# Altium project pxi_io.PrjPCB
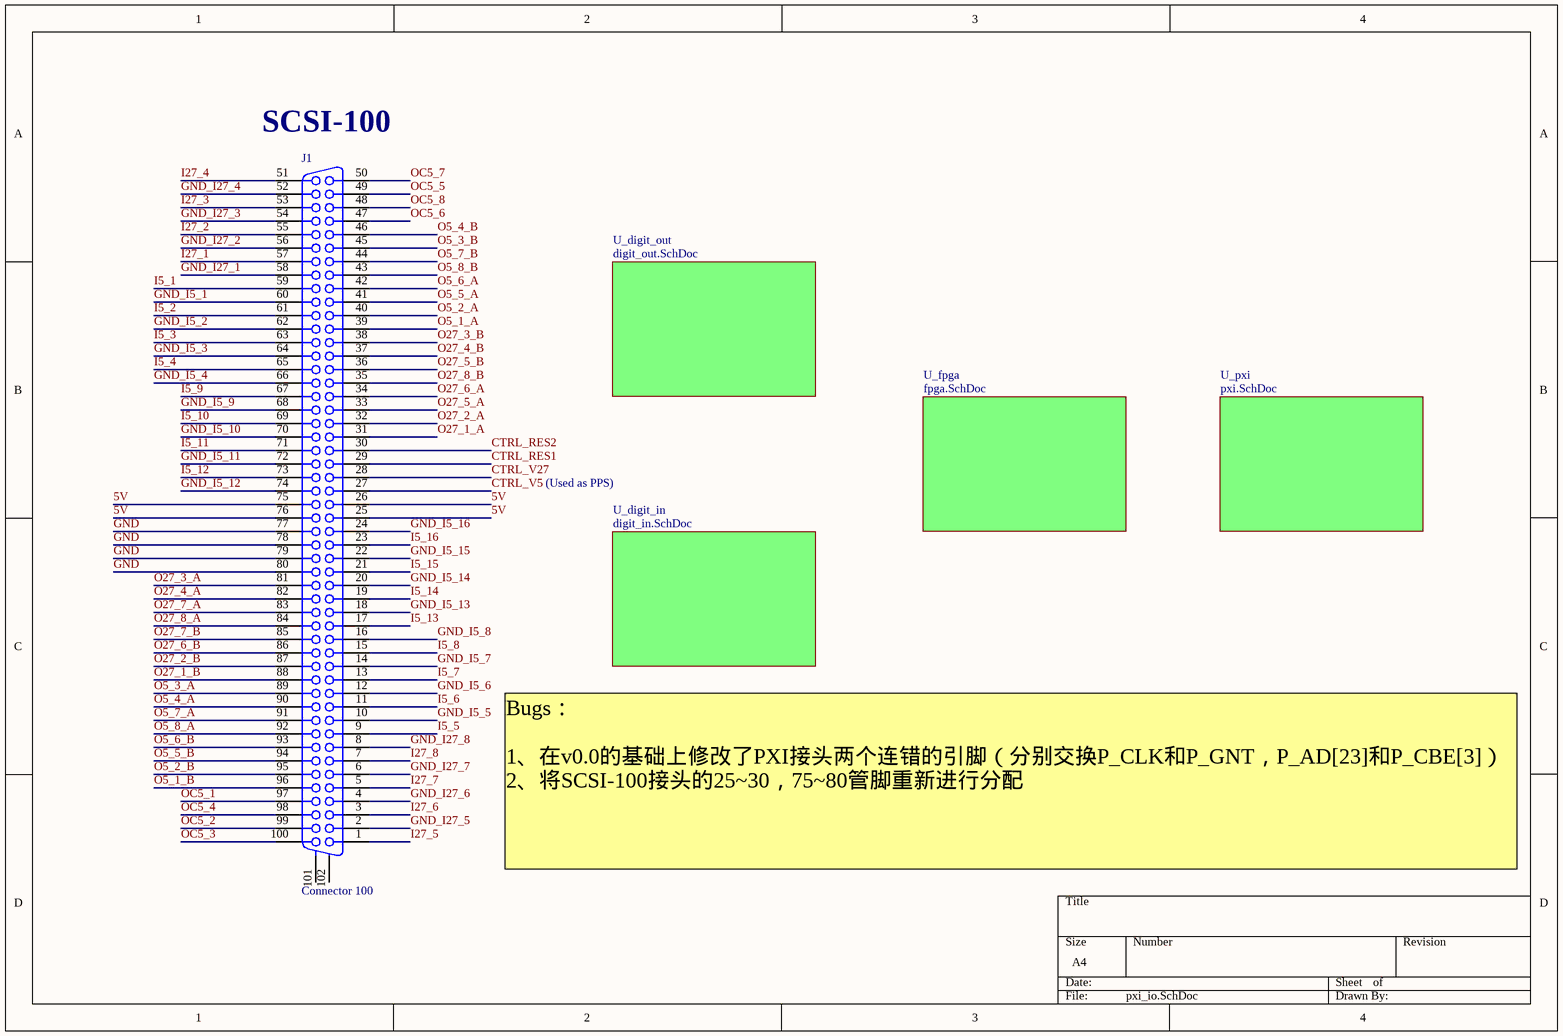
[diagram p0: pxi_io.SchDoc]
5 sheets, 257 parts. Net scope: global (net labels, ports and power ports of the same name join across sheets).
Board file: pxi_io.PcbDoc
Sheets:
  pxi_io.SchDoc
    U_fpga = fpga.SchDoc
    U_digit_out = digit_out.SchDoc
    U_digit_in = digit_in.SchDoc
    U_pxi = pxi.SchDoc

## Sheet pxi_io.SchDoc
size A4

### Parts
J1  Connector 100  [SCSI-100]

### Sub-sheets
U_digit_in = digit_in.SchDoc: no entries
U_digit_out = digit_out.SchDoc: no entries
U_fpga = fpga.SchDoc: no entries
U_pxi = pxi.SchDoc: no entries

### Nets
5V: J1.25 J1.26 J1.75 J1.76
GND: J1.77 J1.78 J1.79 J1.80
CTRL_RES1: J1.29
CTRL_RES2: J1.30
CTRL_V5: J1.27
CTRL_V27: J1.28
GND_I5_1: J1.60
GND_I5_2: J1.62
GND_I5_3: J1.64
GND_I5_4: J1.66
GND_I5_5: J1.10
GND_I5_6: J1.12
GND_I5_7: J1.14
GND_I5_8: J1.16
GND_I5_9: J1.68
GND_I5_10: J1.70
GND_I5_11: J1.72
GND_I5_12: J1.74
GND_I5_13: J1.18
GND_I5_14: J1.20
GND_I5_15: J1.22
GND_I5_16: J1.24
GND_I27_1: J1.58
GND_I27_2: J1.56
GND_I27_3: J1.54
GND_I27_4: J1.52
GND_I27_5: J1.2
GND_I27_6: J1.4
GND_I27_7: J1.6
GND_I27_8: J1.8
I5_1: J1.59
I5_2: J1.61
I5_3: J1.63
I5_4: J1.65
I5_5: J1.9
I5_6: J1.11
I5_7: J1.13
I5_8: J1.15
I5_9: J1.67
I5_10: J1.69
I5_11: J1.71
I5_12: J1.73
I5_13: J1.17
I5_14: J1.19
I5_15: J1.21
I5_16: J1.23
I27_1: J1.57
I27_2: J1.55
I27_3: J1.53
I27_4: J1.51
I27_5: J1.1
I27_6: J1.3
I27_7: J1.5
I27_8: J1.7
O5_1_A: J1.39
O5_1_B: J1.96
O5_2_A: J1.40
O5_2_B: J1.95
O5_3_A: J1.89
O5_3_B: J1.45
O5_4_A: J1.90
O5_4_B: J1.46
O5_5_A: J1.41
O5_5_B: J1.94
O5_6_A: J1.42
O5_6_B: J1.93
O5_7_A: J1.91
O5_7_B: J1.44
O5_8_A: J1.92
O5_8_B: J1.43
O27_1_A: J1.31
O27_1_B: J1.88
O27_2_A: J1.32
O27_2_B: J1.87
O27_3_A: J1.81
O27_3_B: J1.38
O27_4_A: J1.82
O27_4_B: J1.37
O27_5_A: J1.33
O27_5_B: J1.36
O27_6_A: J1.34
O27_6_B: J1.86
O27_7_A: J1.83
O27_7_B: J1.85
O27_8_A: J1.84
O27_8_B: J1.35
OC5_1: J1.97
OC5_2: J1.99
OC5_3: J1.100
OC5_4: J1.98
OC5_5: J1.49
OC5_6: J1.47
OC5_7: J1.50
OC5_8: J1.48

Not connected (* = marked no-connect by the designer): J1 101(MH1) 102(MH2)

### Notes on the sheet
- (near J1) SCSI-100
- (Used as PPS)
- Bugs：
  1、在v0.0的基础上修改了PXI接头两个连错的引脚（分别交换P_CLK和P_GNT，P_AD[23]和P_CBE[3]）
  2、将SCSI-100接头的25~30，75~80管脚重新进行分配

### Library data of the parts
J1 = Connector 100: Receptacle Header Assemby; PackageDocument: B; Positions: 100

## Sheet fpga.SchDoc
size A2
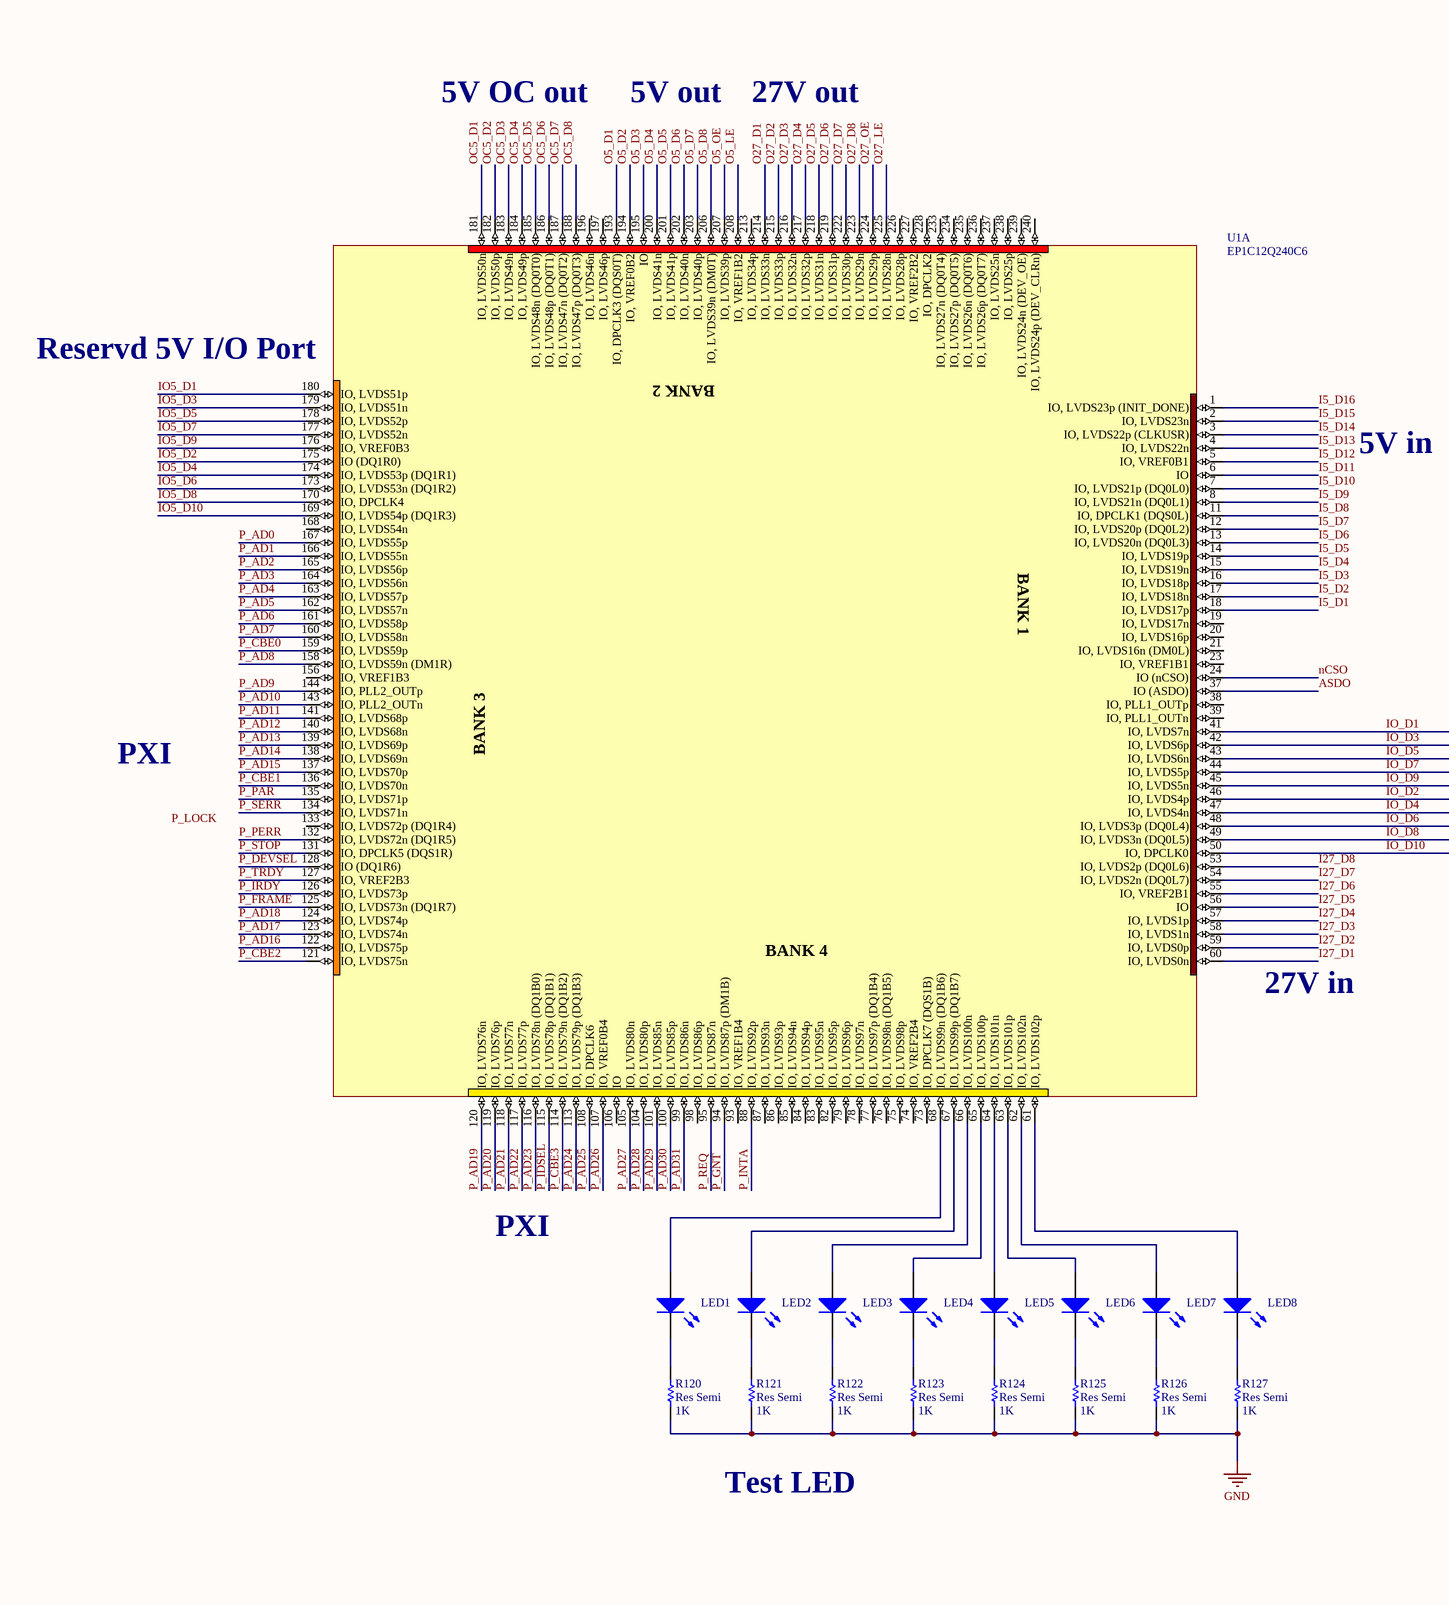
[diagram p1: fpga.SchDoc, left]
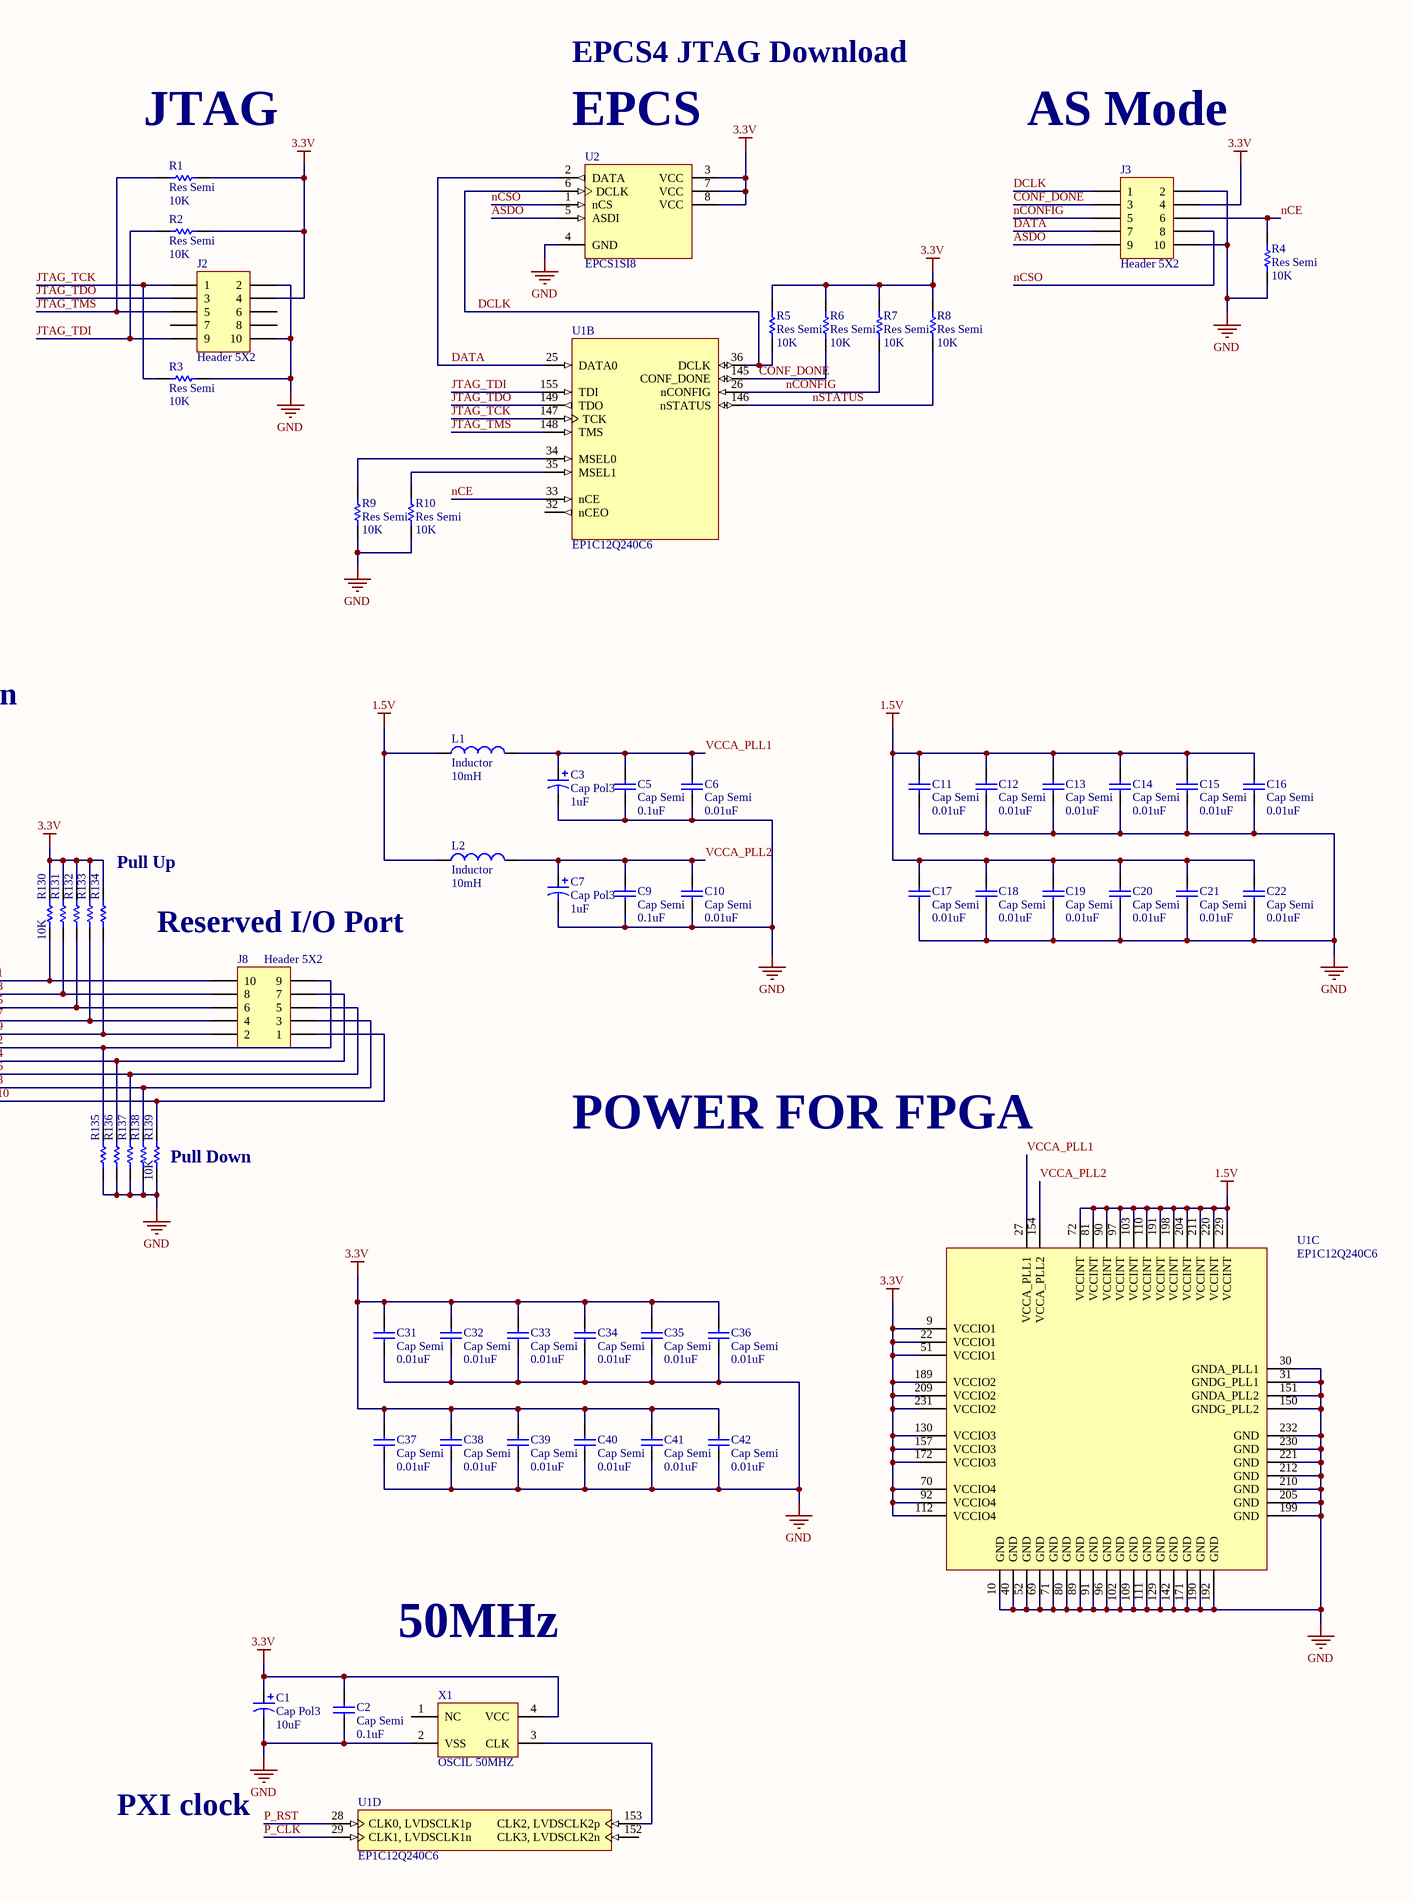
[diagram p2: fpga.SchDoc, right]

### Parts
C1  Cap Pol3  value 10uF  [CC3216-1206]
C2  Cap Semi  value 0.1uF  [1608[0603]]
C3  Cap Pol3  value 1uF  [CC3216-1206]
C5  Cap Semi  value 0.1uF  [1608[0603]]
C6  Cap Semi  value 0.01uF  [1608[0603]]
C7  Cap Pol3  value 1uF  [CC3216-1206]
C9  Cap Semi  value 0.1uF  [1608[0603]]
C10  Cap Semi  value 0.01uF  [1608[0603]]
C11  Cap Semi  value 0.01uF  [1608[0603]]
C12  Cap Semi  value 0.01uF  [1608[0603]]
C13  Cap Semi  value 0.01uF  [1608[0603]]
C14  Cap Semi  value 0.01uF  [1608[0603]]
C15  Cap Semi  value 0.01uF  [1608[0603]]
C16  Cap Semi  value 0.01uF  [1608[0603]]
C17  Cap Semi  value 0.01uF  [1608[0603]]
C18  Cap Semi  value 0.01uF  [1608[0603]]
C19  Cap Semi  value 0.01uF  [1608[0603]]
C20  Cap Semi  value 0.01uF  [1608[0603]]
C21  Cap Semi  value 0.01uF  [1608[0603]]
C22  Cap Semi  value 0.01uF  [1608[0603]]
C31  Cap Semi  value 0.01uF  [1608[0603]]
C32  Cap Semi  value 0.01uF  [1608[0603]]
C33  Cap Semi  value 0.01uF  [1608[0603]]
C34  Cap Semi  value 0.01uF  [1608[0603]]
C35  Cap Semi  value 0.01uF  [1608[0603]]
C36  Cap Semi  value 0.01uF  [1608[0603]]
C37  Cap Semi  value 0.01uF  [1608[0603]]
C38  Cap Semi  value 0.01uF  [1608[0603]]
C39  Cap Semi  value 0.01uF  [1608[0603]]
C40  Cap Semi  value 0.01uF  [1608[0603]]
C41  Cap Semi  value 0.01uF  [1608[0603]]
C42  Cap Semi  value 0.01uF  [1608[0603]]
J2  Header 5X2  [HDR2X5_JTAG]
J3  Header 5X2  [HDR2X5_JTAG]
J8  Header 5X2  [HDR2X5]
L1  Inductor  value 10mH  [C1608-0603]
L2  Inductor  value 10mH  [C1608-0603]
LED1  LED2  [D1608-0603]  (value not drawn)
LED2  LED2  [D1608-0603]  (value not drawn)
LED3  LED2  [D1608-0603]  (value not drawn)
LED4  LED2  [D1608-0603]  (value not drawn)
LED5  LED2  [D1608-0603]  (value not drawn)
LED6  LED2  [D1608-0603]  (value not drawn)
LED7  LED2  [D1608-0603]  (value not drawn)
LED8  LED2  [D1608-0603]  (value not drawn)
R1  Res Semi  value 10K  [1608[0603]]
R2  Res Semi  value 10K  [1608[0603]]
R3  Res Semi  value 10K  [1608[0603]]
R4  Res Semi  value 10K  [1608[0603]]
R5  Res Semi  value 10K  [1608[0603]]
R6  Res Semi  value 10K  [1608[0603]]
R7  Res Semi  value 10K  [1608[0603]]
R8  Res Semi  value 10K  [1608[0603]]
R9  Res Semi  value 10K  [1608[0603]]
R10  Res Semi  value 10K  [1608[0603]]
R120  Res Semi  value 1K  [1608[0603]]
R121  Res Semi  value 1K  [1608[0603]]
R122  Res Semi  value 1K  [1608[0603]]
R123  Res Semi  value 1K  [1608[0603]]
R124  Res Semi  value 1K  [1608[0603]]
R125  Res Semi  value 1K  [1608[0603]]
R126  Res Semi  value 1K  [1608[0603]]
R127  Res Semi  value 1K  [1608[0603]]
R130  value 10K  [1608[0603]]  (hidden comment: Res Semi)
R131  Res Semi  [1608[0603]]  (value not drawn)
R132  Res Semi  [1608[0603]]  (value not drawn)
R133  Res Semi  [1608[0603]]  (value not drawn)
R134  Res Semi  [1608[0603]]  (value not drawn)
R135  Res Semi  [1608[0603]]  (value not drawn)
R136  Res Semi  [1608[0603]]  (value not drawn)
R137  Res Semi  [1608[0603]]  (value not drawn)
R138  Res Semi  [1608[0603]]  (value not drawn)
R139  value 10K  [1608[0603]]  (hidden comment: Res Semi)
U1  EP1C12Q240C6  [PQFP240]  (parts A,B,C,D of 4)
U2  EPCS1SI8  [SOIC8_L]
X1  OSCIL 50MHZ  [OSC -BIG]

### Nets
1.5V: C11.2 C12.2 C13.2 C14.2 C15.2 C16.2 C17.2 C18.2 C19.2 C20.2 C21.2 C22.2 L1.1 L2.1 U1.72(VCCINT) U1.81(VCCINT) U1.90(VCCINT) U1.97(VCCINT) U1.103(VCCINT) U1.110(VCCINT) U1.191(VCCINT) U1.198(VCCINT) U1.204(VCCINT) U1.211(VCCINT) U1.220(VCCINT) U1.229(VCCINT)
3.3V: C1.1 C2.2 C31.2 C32.2 C33.2 C34.2 C35.2 C36.2 C37.2 C38.2 C39.2 C40.2 C41.2 C42.2 J2.4 J3.4 R1.2 R2.2 R5.1 R6.1 R7.1 R8.1 R130.2 R131.2 R132.2 R133.2 R134.2 U1.9(VCCIO1) U1.22(VCCIO1) U1.51(VCCIO1) U1.70(VCCIO4) U1.92(VCCIO4) U1.112(VCCIO4) U1.130(VCCIO3) U1.157(VCCIO3) U1.172(VCCIO3) U1.189(VCCIO2) U1.209(VCCIO2) U1.231(VCCIO2) U2.3(VCC) U2.7(VCC) U2.8(VCC) X1.4(VCC)
GND: C1.2 C2.1 C3.2 C5.1 C6.1 C7.2 C9.1 C10.1 C11.1 C12.1 C13.1 C14.1 C15.1 C16.1 C17.1 C18.1 C19.1 C20.1 C21.1 C22.1 C31.1 C32.1 C33.1 C34.1 C35.1 C36.1 C37.1 C38.1 C39.1 C40.1 C41.1 C42.1 J2.2 J2.10 J3.2 J3.10 R3.2 R4.1 R9.2 R10.2 R120.2 R121.2 R122.2 R123.2 R124.2 R125.2 R126.2 R127.2 R135.1 R136.1 R137.1 R138.1 R139.1 U1.10(GND) U1.30(GNDA_PLL1) U1.31(GNDG_PLL1) U1.40(GND) U1.52(GND) U1.69(GND) U1.71(GND) U1.80(GND) U1.89(GND) U1.91(GND) U1.96(GND) U1.102(GND) U1.109(GND) U1.111(GND) U1.129(GND) U1.142(GND) U1.150(GNDG_PLL2) U1.151(GNDA_PLL2) U1.171(GND) U1.190(GND) U1.192(GND) U1.199(GND) U1.205(GND) U1.210(GND) U1.212(GND) U1.221(GND) U1.230(GND) U1.232(GND) U2.4(GND) X1.2(VSS)
ASDO: J3.9 U1.37(IO_(ASDO)) U2.5(ASDI)
CONF_DONE: J3.3 R6.2 U1.145(CONF_DONE)
DATA: J3.7 U1.25(DATA0) U2.2(DATA)
DCLK: J3.1 R5.2 U1.36(DCLK) U2.6(DCLK)
I5_D1: U1.18(IO,_LVDS17p)
I5_D2: U1.17(IO,_LVDS18n)
I5_D3: U1.16(IO,_LVDS18p)
I5_D4: U1.15(IO,_LVDS19n)
I5_D5: U1.14(IO,_LVDS19p)
I5_D6: U1.13(IO,_LVDS20n_(DQ0L3))
I5_D7: U1.12(IO,_LVDS20p_(DQ0L2))
I5_D8: U1.11(IO,_DPCLK1_(DQS0L))
I5_D9: U1.8(IO,_LVDS21n_(DQ0L1))
I5_D10: U1.7(IO,_LVDS21p_(DQ0L0))
I5_D11: U1.6(IO)
I5_D12: U1.5(IO,_VREF0B1)
I5_D13: U1.4(IO,_LVDS22n)
I5_D14: U1.3(IO,_LVDS22p_(CLKUSR))
I5_D15: U1.2(IO,_LVDS23n)
I5_D16: U1.1(IO,_LVDS23p_(INIT_DONE))
I27_D1: U1.60(IO,_LVDS0n)
I27_D2: U1.59(IO,_LVDS0p)
I27_D3: U1.58(IO,_LVDS1n)
I27_D4: U1.57(IO,_LVDS1p)
I27_D5: U1.56(IO)
I27_D6: U1.55(IO,_VREF2B1)
I27_D7: U1.54(IO,_LVDS2n_(DQ0L7))
I27_D8: U1.53(IO,_LVDS2p_(DQ0L6))
IO5_D1: U1.180(IO,_LVDS51p)
IO5_D2: U1.175(IO_(DQ1R0))
IO5_D3: U1.179(IO,_LVDS51n)
IO5_D4: U1.174(IO,_LVDS53p_(DQ1R1))
IO5_D5: U1.178(IO,_LVDS52p)
IO5_D6: U1.173(IO,_LVDS53n_(DQ1R2))
IO5_D7: U1.177(IO,_LVDS52n)
IO5_D8: U1.170(IO,_DPCLK4)
IO5_D9: U1.176(IO,_VREF0B3)
IO5_D10: U1.169(IO,_LVDS54p_(DQ1R3))
IO_D1: J8.10 R130.1 U1.41(IO,_LVDS7n)
IO_D2: J8.9 R135.2 U1.46(IO,_LVDS4p)
IO_D3: J8.8 R131.1 U1.42(IO,_LVDS6p)
IO_D4: J8.7 R136.2 U1.47(IO,_LVDS4n)
IO_D5: J8.6 R132.1 U1.43(IO,_LVDS6n)
IO_D6: J8.5 R137.2 U1.48(IO,_LVDS3p_(DQ0L4))
IO_D7: J8.4 R133.1 U1.44(IO,_LVDS5p)
IO_D8: J8.3 R138.2 U1.49(IO,_LVDS3n_(DQ0L5))
IO_D9: J8.2 R134.1 U1.45(IO,_LVDS5n)
IO_D10: J8.1 R139.2 U1.50(IO,_DPCLK0)
JTAG_TCK: J2.1 R3.1 U1.147(TCK)
JTAG_TDI: J2.9 R2.1 U1.155(TDI)
JTAG_TDO: J2.3 U1.149(TDO)
JTAG_TMS: J2.5 R1.1 U1.148(TMS)
nCE: J3.6 R4.2 U1.33(nCE)
nCONFIG: J3.5 R7.2 U1.26(nCONFIG)
nCSO: J3.8 U1.24(IO_(nCSO)) U2.1(nCS)
nSTATUS: R8.2 U1.146(nSTATUS)
O5_D1: U1.193(IO,_DPCLK3_(DQS0T))
O5_D2: U1.194(IO,_VREF0B2)
O5_D3: U1.195(IO)
O5_D4: U1.200(IO,_LVDS41n)
O5_D5: U1.201(IO,_LVDS41p)
O5_D6: U1.202(IO,_LVDS40n)
O5_D7: U1.203(IO,_LVDS40p)
O5_D8: U1.206(IO,_LVDS39n_(DM0T))
O5_LE: U1.208(IO,_VREF1B2)
O5_OE: U1.207(IO,_LVDS39p)
O27_D1: U1.214(IO,_LVDS33n)
O27_D2: U1.215(IO,_LVDS33p)
O27_D3: U1.216(IO,_LVDS32n)
O27_D4: U1.217(IO,_LVDS32p)
O27_D5: U1.218(IO,_LVDS31n)
O27_D6: U1.219(IO,_LVDS31p)
O27_D7: U1.222(IO,_LVDS30p)
O27_D8: U1.223(IO,_LVDS29n)
O27_LE: U1.225(IO,_LVDS28n)
O27_OE: U1.224(IO,_LVDS29p)
OC5_D1: U1.181(IO,_LVDS50n)
OC5_D2: U1.182(IO,_LVDS50p)
OC5_D3: U1.183(IO,_LVDS49n)
OC5_D4: U1.184(IO,_LVDS49p)
OC5_D5: U1.185(IO,_LVDS48n_(DQ0T0))
OC5_D6: U1.186(IO,_LVDS48p_(DQ0T1))
OC5_D7: U1.187(IO,_LVDS47n_(DQ0T2))
OC5_D8: U1.188(IO,_LVDS47p_(DQ0T3))
P_AD0: U1.167(IO,_LVDS55p)
P_AD1: U1.166(IO,_LVDS55n)
P_AD2: U1.165(IO,_LVDS56p)
P_AD3: U1.164(IO,_LVDS56n)
P_AD4: U1.163(IO,_LVDS57p)
P_AD5: U1.162(IO,_LVDS57n)
P_AD6: U1.161(IO,_LVDS58p)
P_AD7: U1.160(IO,_LVDS58n)
P_AD8: U1.158(IO,_LVDS59n_(DM1R))
P_AD9: U1.144(IO,_PLL2_OUTp)
P_AD10: U1.143(IO,_PLL2_OUTn)
P_AD11: U1.141(IO,_LVDS68p)
P_AD12: U1.140(IO,_LVDS68n)
P_AD13: U1.139(IO,_LVDS69p)
P_AD14: U1.138(IO,_LVDS69n)
P_AD15: U1.137(IO,_LVDS70p)
P_AD16: U1.122(IO,_LVDS75p)
P_AD17: U1.123(IO,_LVDS74n)
P_AD18: U1.124(IO,_LVDS74p)
P_AD19: U1.120(IO,_LVDS76n)
P_AD20: U1.119(IO,_LVDS76p)
P_AD21: U1.118(IO,_LVDS77n)
P_AD22: U1.117(IO,_LVDS77p)
P_AD23: U1.116(IO,_LVDS78n_(DQ1B0))
P_AD24: U1.113(IO,_LVDS79p_(DQ1B3))
P_AD25: U1.108(IO,_DPCLK6)
P_AD26: U1.107(IO,_VREF0B4)
P_AD27: U1.105(IO,_LVDS80n)
P_AD28: U1.104(IO,_LVDS80p)
P_AD29: U1.101(IO,_LVDS85n)
P_AD30: U1.100(IO,_LVDS85p)
P_AD31: U1.99(IO,_LVDS86n)
P_CBE0: U1.159(IO,_LVDS59p)
P_CBE1: U1.136(IO,_LVDS70n)
P_CBE2: U1.121(IO,_LVDS75n)
P_CBE3: U1.114(IO,_LVDS79n_(DQ1B2))
P_CLK: U1.29(CLK1,_LVDSCLK1n)
P_DEVSEL: U1.128(IO_(DQ1R6))
P_FRAME: U1.125(IO,_LVDS73n_(DQ1R7))
P_GNT: U1.94(IO,_LVDS87p_(DM1B))
P_IDSEL: U1.115(IO,_LVDS78p_(DQ1B1))
P_INTA: U1.88(IO,_LVDS92p)
P_IRDY: U1.126(IO,_LVDS73p)
P_PAR: U1.135(IO,_LVDS71p)
P_PERR: U1.132(IO,_LVDS72n_(DQ1R5))
P_REQ: U1.95(IO,_LVDS87n)
P_RST: U1.28(CLK0,_LVDSCLK1p)
P_SERR: U1.134(IO,_LVDS71n)
P_STOP: U1.131(IO,_DPCLK5_(DQS1R))
P_TRDY: U1.127(IO,_VREF2B3)
VCCA_PLL1: C3.1 C5.2 C6.2 L1.2 U1.27(VCCA_PLL1)
VCCA_PLL2: C7.1 C9.2 C10.2 L2.2 U1.154(VCCA_PLL2)
NetLED1_1: LED1.1(A) U1.68(IO,_LVDS99n_(DQ1B6))
NetLED1_2: LED1.2(K) R120.1
NetLED2_1: LED2.1(A) U1.67(IO,_LVDS99p_(DQ1B7))
NetLED2_2: LED2.2(K) R121.1
NetLED3_1: LED3.1(A) U1.66(IO,_LVDS100n)
NetLED3_2: LED3.2(K) R122.1
NetLED4_1: LED4.1(A) U1.65(IO,_LVDS100p)
NetLED4_2: LED4.2(K) R123.1
NetLED5_1: LED5.1(A) U1.64(IO,_LVDS101n)
NetLED5_2: LED5.2(K) R124.1
NetLED6_1: LED6.1(A) U1.63(IO,_LVDS101p)
NetLED6_2: LED6.2(K) R125.1
NetLED7_1: LED7.1(A) U1.62(IO,_LVDS102n)
NetLED7_2: LED7.2(K) R126.1
NetLED8_1: LED8.1(A) U1.61(IO,_LVDS102p)
NetLED8_2: LED8.2(K) R127.1
NetR9_1: R9.1 U1.34(MSEL0)
NetR10_1: R10.1 U1.35(MSEL1)
NetU1_153: U1.153(CLK2,_LVDSCLK2p) X1.3(CLK)

Not connected (* = marked no-connect by the designer): J2 6 7 8; U1 19(IO,_LVDS17n) 20(IO,_LVDS16p) 21(IO,_LVDS16n_(DM0L)) 23(IO,_VREF1B1) 32(nCEO) 38(IO,_PLL1_OUTp) 39(IO,_PLL1_OUTn) 73(IO,_DPCLK7_(DQS1B)) 74(IO,_VREF2B4) 75(IO,_LVDS98p) 76(IO,_LVDS98n_(DQ1B5)) 77(IO,_LVDS97p_(DQ1B4)) 78(IO,_LVDS97n) 79(IO,_LVDS96p) 82(IO,_LVDS95p) 83(IO,_LVDS95n) 84(IO,_LVDS94p) 85(IO,_LVDS94n) 86(IO,_LVDS93p) 87(IO,_LVDS93n) 93(IO,_VREF1B4) 98(IO,_LVDS86p) 106(IO) 133(IO,_LVDS72p_(DQ1R4)) 152(CLK3,_LVDSCLK2n) 156(IO,_VREF1B3) 168(IO,_LVDS54n) 196(IO,_LVDS46n) 197(IO,_LVDS46p) 213(IO,_LVDS34p) 226(IO,_LVDS28p) 227(IO,_VREF2B2) 228(IO,_DPCLK2) 233(IO,_LVDS27n_(DQ0T4)) 234(IO,_LVDS27p_(DQ0T5)) 235(IO,_LVDS26n_(DQ0T6)) 236(IO,_LVDS26p_(DQ0T7)) 237(IO,_LVDS25n) 238(IO,_LVDS25p) 239(IO,_LVDS24n_(DEV_OE)) 240(IO,_LVDS24p_(DEV_CLRn)); X1 1(NC)

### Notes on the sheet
- EPCS4 JTAG Download
- (near R1) JTAG
- (near U2) EPCS
- AS Mode
- 5V OC out
- 5V out
- 27V out
- (near U1) Reservd 5V I/O Port
- 5V in
- Pull Up
- Reserved I/O Port
- PXI
- POWER FOR FPGA
- (near R139) Pull Down
- 27V in
- 50MHz
- Test LED
- PXI clock
- Labels drawn without touching a wire or pin: P_LOCK

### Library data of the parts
C1 C3 C7 = Cap Pol3: Polarized Capacitor (Surface Mount)
C2 C5 C6 C9-C22 C31-C42 = Cap Semi: Capacitor (Semiconductor SIM Model)
J2 J3 J8 = Header 5X2: Header, 5-Pin, Dual row
L1 L2 = Inductor: Code_IEC: 1005
LED1-LED8 = LED2: Typical RED, GREEN, YELLOW, AMBER GaAs LED
R1-R10 R120-R127 R130 R139 = Res Semi: Semiconductor Resistor
R131-R138 = Res Semi: Semiconductor Resistor; Value: 10K
U1 = EP1C12Q240C6: Cyclone Family, 1.5V FPGA, 173 I/O Pins, 2 x PLLs, Commercial Grade, Speed Grade 6; Package Information: Latest Revision: ver11.0, Feb-2003; Code - JEDEC: MS-029-GA
U2 = EPCS1SI8: EPCS1 Series, In-system programmable 3.3V serial configuration device, 8-Pin SOIC, 1-Megabit, Industrial Grade; Configures: Cyclone II, Stratix II, & Cyclone Devices
X1 = OSCIL

## Sheet digit_out.SchDoc
size A2
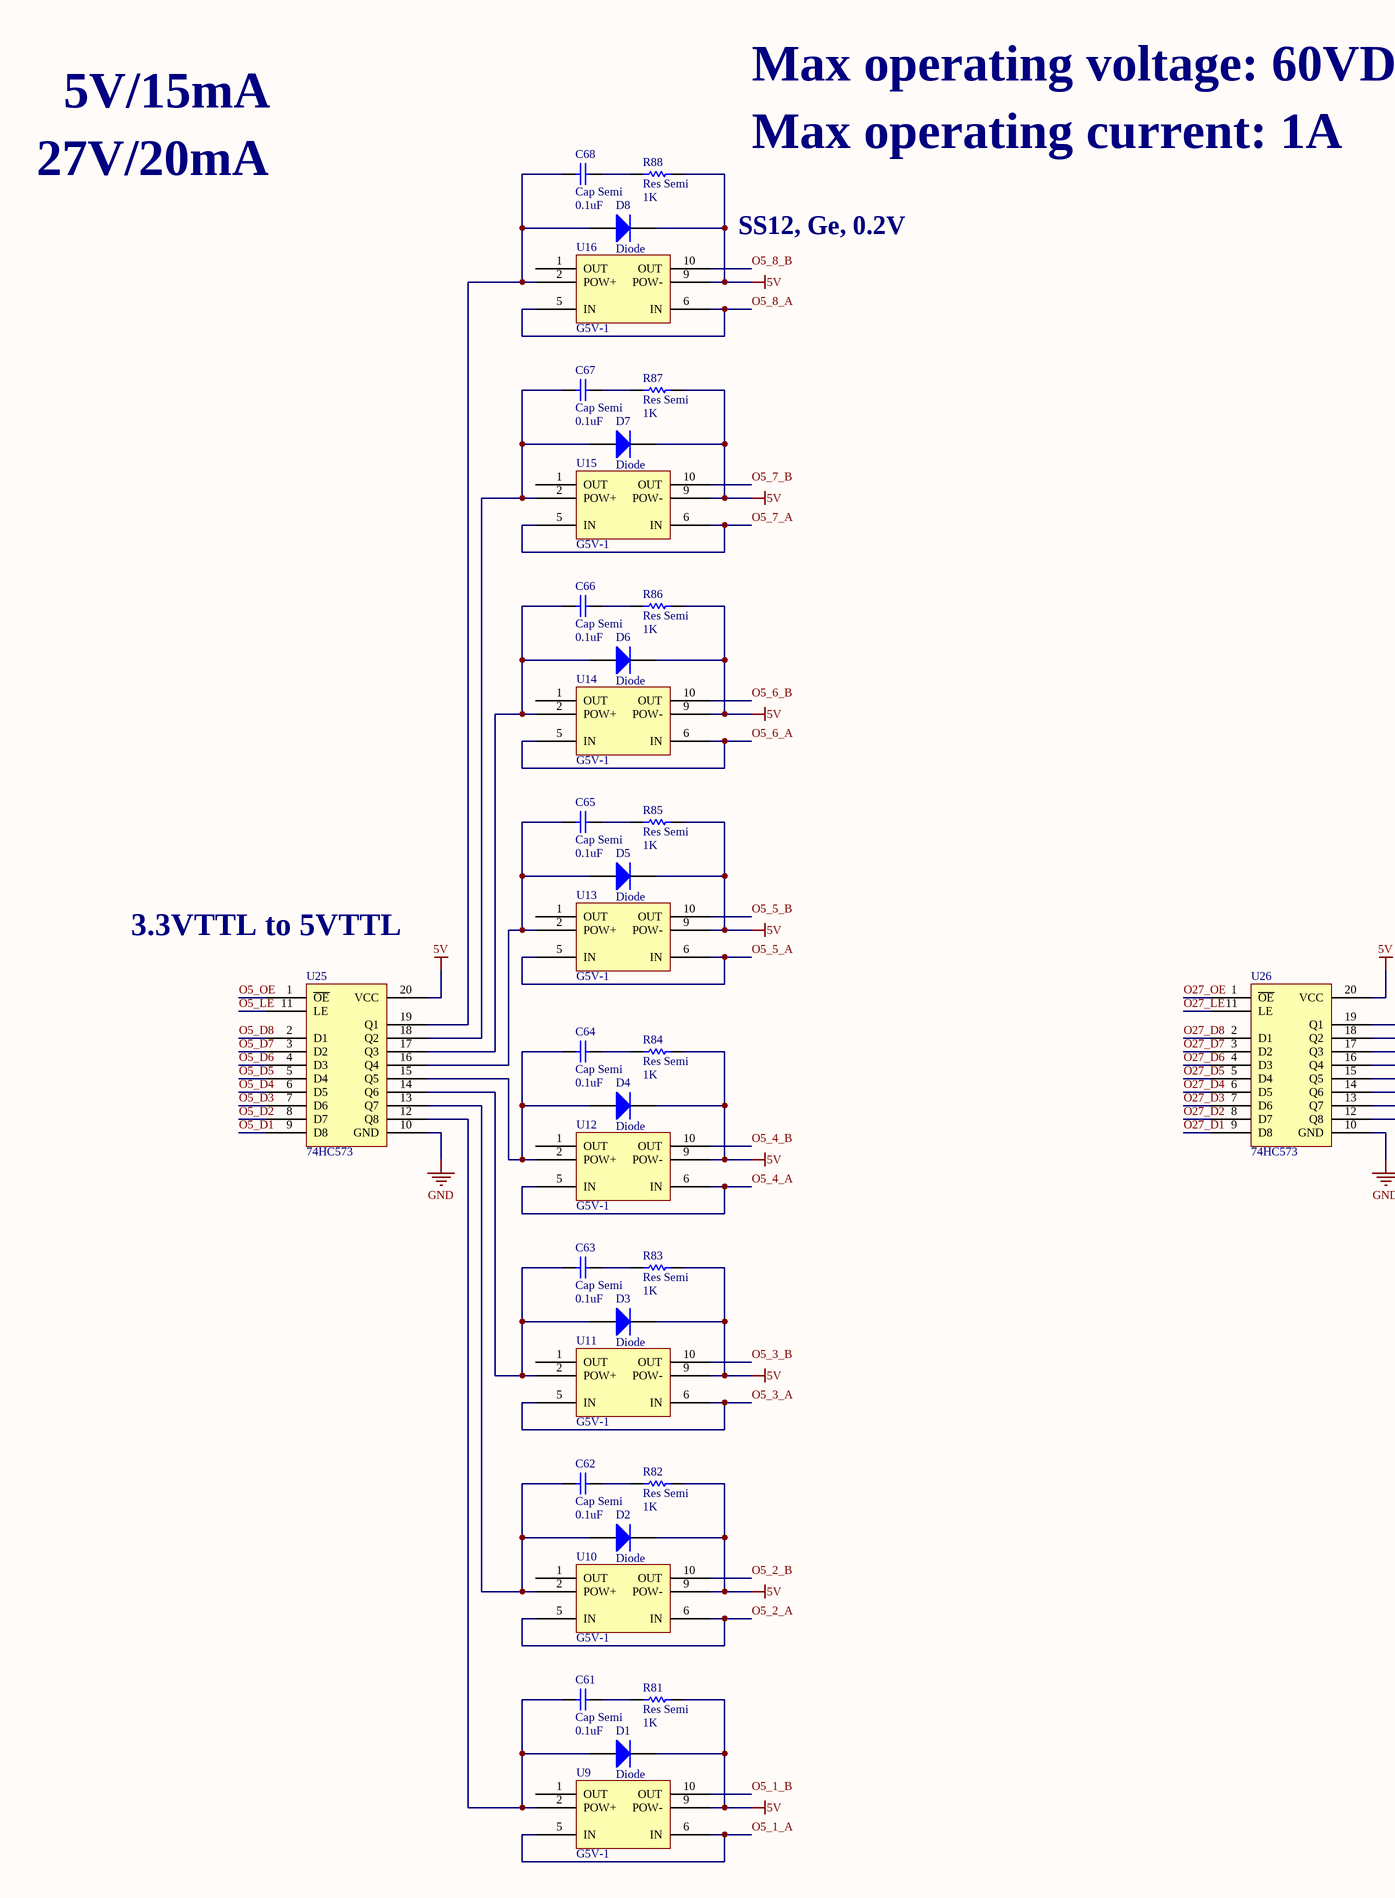
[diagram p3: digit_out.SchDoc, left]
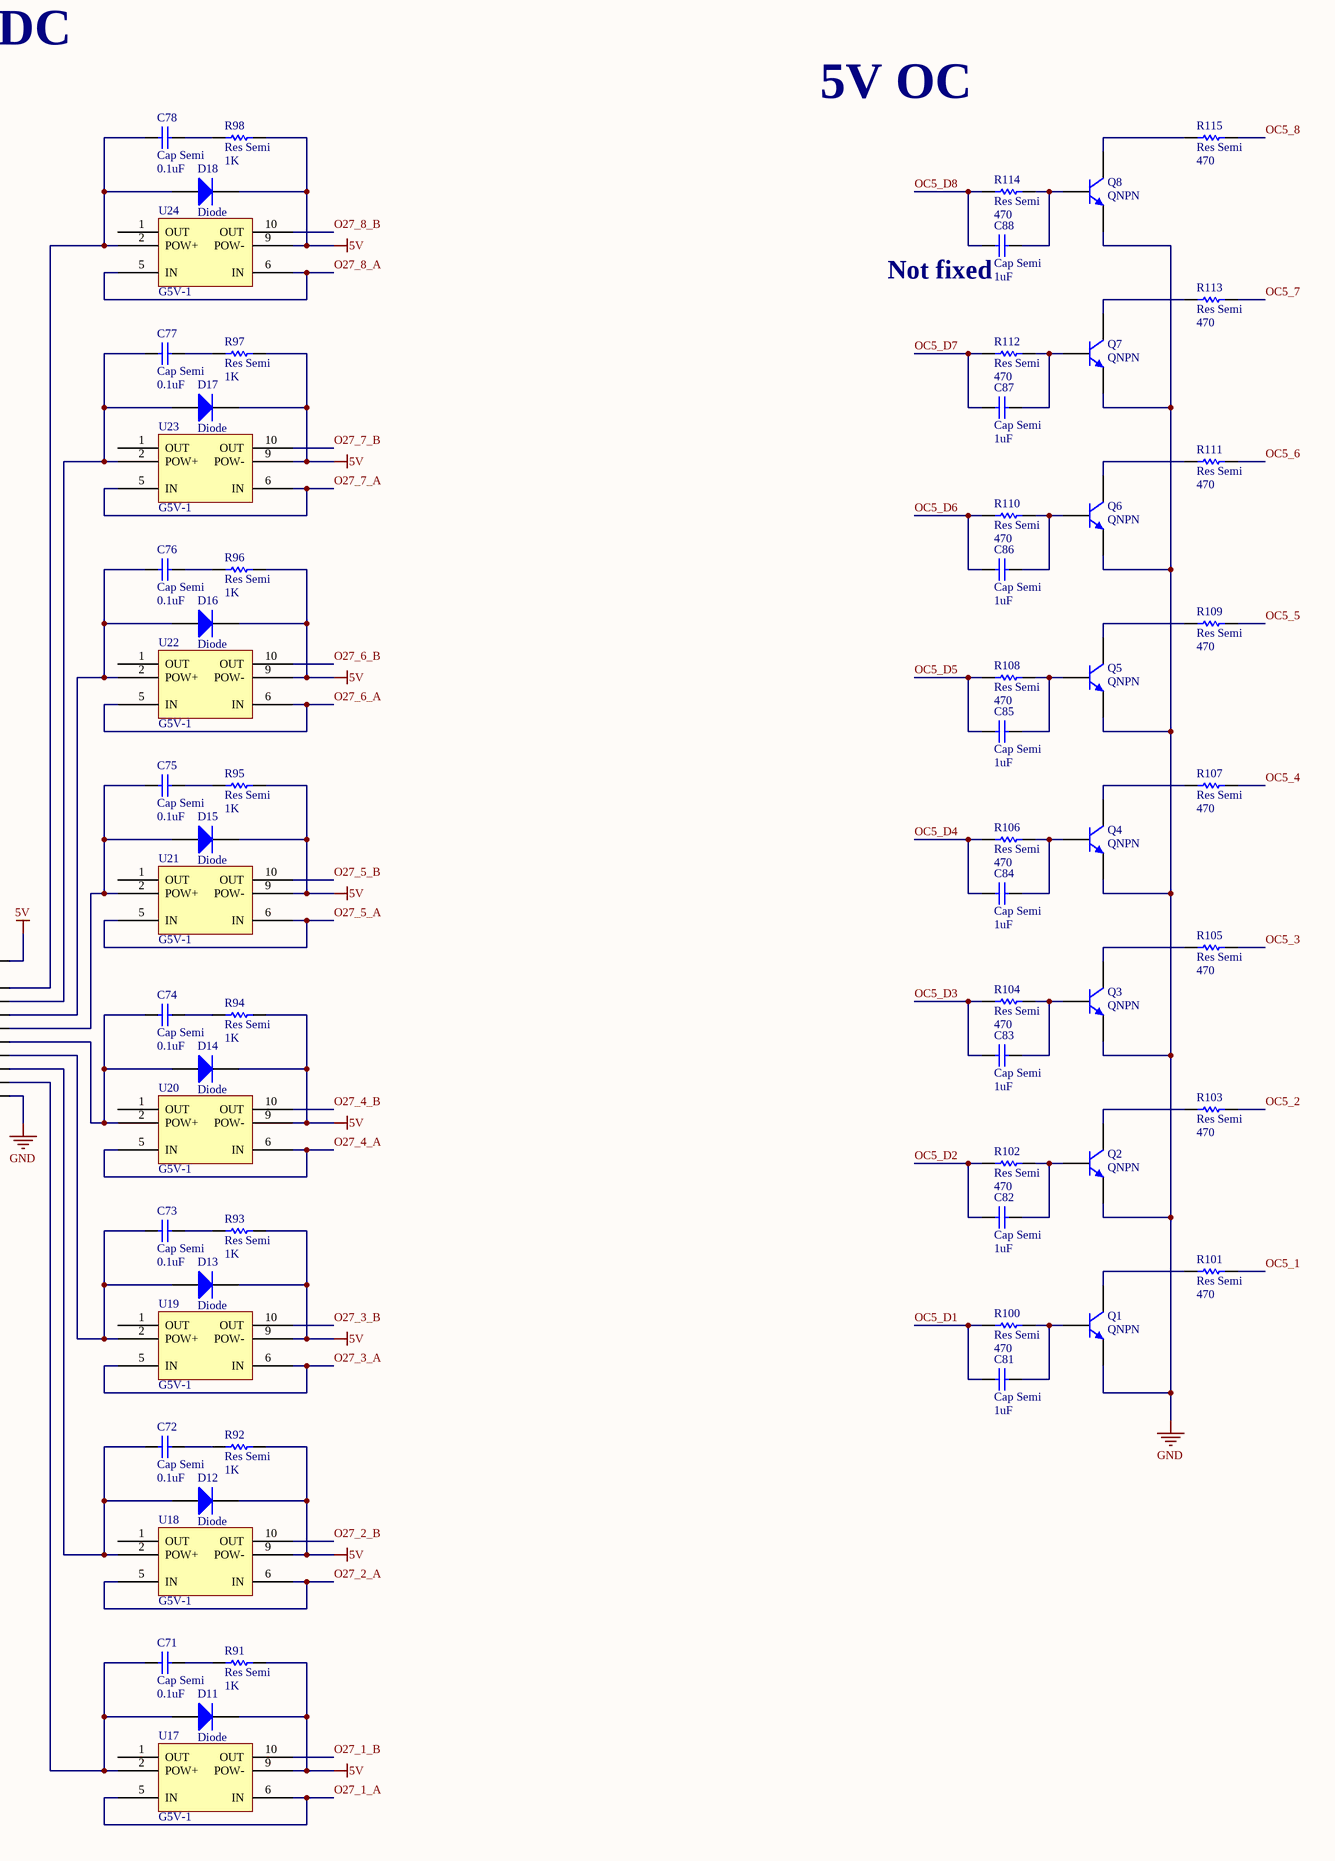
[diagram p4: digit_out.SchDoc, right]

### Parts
C61  Cap Semi  value 0.1uF  [1608[0603]]
C62  Cap Semi  value 0.1uF  [1608[0603]]
C63  Cap Semi  value 0.1uF  [1608[0603]]
C64  Cap Semi  value 0.1uF  [1608[0603]]
C65  Cap Semi  value 0.1uF  [1608[0603]]
C66  Cap Semi  value 0.1uF  [1608[0603]]
C67  Cap Semi  value 0.1uF  [1608[0603]]
C68  Cap Semi  value 0.1uF  [1608[0603]]
C71  Cap Semi  value 0.1uF  [1608[0603]]
C72  Cap Semi  value 0.1uF  [1608[0603]]
C73  Cap Semi  value 0.1uF  [1608[0603]]
C74  Cap Semi  value 0.1uF  [1608[0603]]
C75  Cap Semi  value 0.1uF  [1608[0603]]
C76  Cap Semi  value 0.1uF  [1608[0603]]
C77  Cap Semi  value 0.1uF  [1608[0603]]
C78  Cap Semi  value 0.1uF  [1608[0603]]
C81  Cap Semi  value 1uF  [1608[0603]]
C82  Cap Semi  value 1uF  [1608[0603]]
C83  Cap Semi  value 1uF  [1608[0603]]
C84  Cap Semi  value 1uF  [1608[0603]]
C85  Cap Semi  value 1uF  [1608[0603]]
C86  Cap Semi  value 1uF  [1608[0603]]
C87  Cap Semi  value 1uF  [1608[0603]]
C88  Cap Semi  value 1uF  [1608[0603]]
D1  Diode  [IN5817]
D2  Diode  [IN5817]
D3  Diode  [IN5817]
D4  Diode  [IN5817]
D5  Diode  [IN5817]
D6  Diode  [IN5817]
D7  Diode  [IN5817]
D8  Diode  [IN5817]
D11  Diode  [IN5817]
D12  Diode  [IN5817]
D13  Diode  [IN5817]
D14  Diode  [IN5817]
D15  Diode  [IN5817]
D16  Diode  [IN5817]
D17  Diode  [IN5817]
D18  Diode  [IN5817]
Q1  QNPN  [SO3]
Q2  QNPN  [SO3]
Q3  QNPN  [SO3]
Q4  QNPN  [SO3]
Q5  QNPN  [SO3]
Q6  QNPN  [SO3]
Q7  QNPN  [SO3]
Q8  QNPN  [SO3]
R81  Res Semi  value 1K  [1608[0603]]
R82  Res Semi  value 1K  [1608[0603]]
R83  Res Semi  value 1K  [1608[0603]]
R84  Res Semi  value 1K  [1608[0603]]
R85  Res Semi  value 1K  [1608[0603]]
R86  Res Semi  value 1K  [1608[0603]]
R87  Res Semi  value 1K  [1608[0603]]
R88  Res Semi  value 1K  [1608[0603]]
R91  Res Semi  value 1K  [1608[0603]]
R92  Res Semi  value 1K  [1608[0603]]
R93  Res Semi  value 1K  [1608[0603]]
R94  Res Semi  value 1K  [1608[0603]]
R95  Res Semi  value 1K  [1608[0603]]
R96  Res Semi  value 1K  [1608[0603]]
R97  Res Semi  value 1K  [1608[0603]]
R98  Res Semi  value 1K  [1608[0603]]
R100  Res Semi  value 470  [1608[0603]]
R101  Res Semi  value 470  [1608[0603]]
R102  Res Semi  value 470  [1608[0603]]
R103  Res Semi  value 470  [1608[0603]]
R104  Res Semi  value 470  [1608[0603]]
R105  Res Semi  value 470  [1608[0603]]
R106  Res Semi  value 470  [1608[0603]]
R107  Res Semi  value 470  [1608[0603]]
R108  Res Semi  value 470  [1608[0603]]
R109  Res Semi  value 470  [1608[0603]]
R110  Res Semi  value 470  [1608[0603]]
R111  Res Semi  value 470  [1608[0603]]
R112  Res Semi  value 470  [1608[0603]]
R113  Res Semi  value 470  [1608[0603]]
R114  Res Semi  value 470  [1608[0603]]
R115  Res Semi  value 470  [1608[0603]]
U9  G5V-1  [G5V-1-DIP]
U10  G5V-1  [G5V-1-DIP]
U11  G5V-1  [G5V-1-DIP]
U12  G5V-1  [G5V-1-DIP]
U13  G5V-1  [G5V-1-DIP]
U14  G5V-1  [G5V-1-DIP]
U15  G5V-1  [G5V-1-DIP]
U16  G5V-1  [G5V-1-DIP]
U17  G5V-1  [G5V-1-DIP]
U18  G5V-1  [G5V-1-DIP]
U19  G5V-1  [G5V-1-DIP]
U20  G5V-1  [G5V-1-DIP]
U21  G5V-1  [G5V-1-DIP]
U22  G5V-1  [G5V-1-DIP]
U23  G5V-1  [G5V-1-DIP]
U24  G5V-1  [G5V-1-DIP]
U25  74HC573  [SOP20]
U26  74HC573  [SOP20]

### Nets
5V: D1.2(K) D2.2(K) D3.2(K) D4.2(K) D5.2(K) D6.2(K) D7.2(K) D8.2(K) D11.2(K) D12.2(K) D13.2(K) D14.2(K) D15.2(K) D16.2(K) D17.2(K) D18.2(K) R81.2 R82.2 R83.2 R84.2 R85.2 R86.2 R87.2 R88.2 R91.2 R92.2 R93.2 R94.2 R95.2 R96.2 R97.2 R98.2 U9.9(POW-) U10.9(POW-) U11.9(POW-) U12.9(POW-) U13.9(POW-) U14.9(POW-) U15.9(POW-) U16.9(POW-) U17.9(POW-) U18.9(POW-) U19.9(POW-) U20.9(POW-) U21.9(POW-) U22.9(POW-) U23.9(POW-) U24.9(POW-) U25.20(VCC) U26.20(VCC)
GND: Q1.3(E) Q2.3(E) Q3.3(E) Q4.3(E) Q5.3(E) Q6.3(E) Q7.3(E) Q8.3(E) U25.10(GND) U26.10(GND)
O5_1_A: U9.5(IN) U9.6(IN)
O5_1_B: U9.10(OUT)
O5_2_A: U10.5(IN) U10.6(IN)
O5_2_B: U10.10(OUT)
O5_3_A: U11.5(IN) U11.6(IN)
O5_3_B: U11.10(OUT)
O5_4_A: U12.5(IN) U12.6(IN)
O5_4_B: U12.10(OUT)
O5_5_A: U13.5(IN) U13.6(IN)
O5_5_B: U13.10(OUT)
O5_6_A: U14.5(IN) U14.6(IN)
O5_6_B: U14.10(OUT)
O5_7_A: U15.5(IN) U15.6(IN)
O5_7_B: U15.10(OUT)
O5_8_A: U16.5(IN) U16.6(IN)
O5_8_B: U16.10(OUT)
O5_D1: U25.9(D8)
O5_D2: U25.8(D7)
O5_D3: U25.7(D6)
O5_D4: U25.6(D5)
O5_D5: U25.5(D4)
O5_D6: U25.4(D3)
O5_D7: U25.3(D2)
O5_D8: U25.2(D1)
O5_LE: U25.11(LE)
O5_OE: U25.1(~{OE})
O27_1_A: U17.5(IN) U17.6(IN)
O27_1_B: U17.10(OUT)
O27_2_A: U18.5(IN) U18.6(IN)
O27_2_B: U18.10(OUT)
O27_3_A: U19.5(IN) U19.6(IN)
O27_3_B: U19.10(OUT)
O27_4_A: U20.5(IN) U20.6(IN)
O27_4_B: U20.10(OUT)
O27_5_A: U21.5(IN) U21.6(IN)
O27_5_B: U21.10(OUT)
O27_6_A: U22.5(IN) U22.6(IN)
O27_6_B: U22.10(OUT)
O27_7_A: U23.5(IN) U23.6(IN)
O27_7_B: U23.10(OUT)
O27_8_A: U24.5(IN) U24.6(IN)
O27_8_B: U24.10(OUT)
O27_D1: U26.9(D8)
O27_D2: U26.8(D7)
O27_D3: U26.7(D6)
O27_D4: U26.6(D5)
O27_D5: U26.5(D4)
O27_D6: U26.4(D3)
O27_D7: U26.3(D2)
O27_D8: U26.2(D1)
O27_LE: U26.11(LE)
O27_OE: U26.1(~{OE})
OC5_1: R101.2
OC5_2: R103.2
OC5_3: R105.2
OC5_4: R107.2
OC5_5: R109.2
OC5_6: R111.2
OC5_7: R113.2
OC5_8: R115.2
OC5_D1: C81.2 R100.1
OC5_D2: C82.2 R102.1
OC5_D3: C83.2 R104.1
OC5_D4: C84.2 R106.1
OC5_D5: C85.2 R108.1
OC5_D6: C86.2 R110.1
OC5_D7: C87.2 R112.1
OC5_D8: C88.2 R114.1
NetC61_1: C61.1 R81.1
NetC61_2: C61.2 D1.1(A) U9.2(POW+) U25.12(Q8)
NetC62_1: C62.1 R82.1
NetC62_2: C62.2 D2.1(A) U10.2(POW+) U25.13(Q7)
NetC63_1: C63.1 R83.1
NetC63_2: C63.2 D3.1(A) U11.2(POW+) U25.14(Q6)
NetC64_1: C64.1 R84.1
NetC64_2: C64.2 D4.1(A) U12.2(POW+) U25.15(Q5)
NetC65_1: C65.1 R85.1
NetC65_2: C65.2 D5.1(A) U13.2(POW+) U25.16(Q4)
NetC66_1: C66.1 R86.1
NetC66_2: C66.2 D6.1(A) U14.2(POW+) U25.17(Q3)
NetC67_1: C67.1 R87.1
NetC67_2: C67.2 D7.1(A) U15.2(POW+) U25.18(Q2)
NetC68_1: C68.1 R88.1
NetC68_2: C68.2 D8.1(A) U16.2(POW+) U25.19(Q1)
NetC71_1: C71.1 R91.1
NetC71_2: C71.2 D11.1(A) U17.2(POW+) U26.12(Q8)
NetC72_1: C72.1 R92.1
NetC72_2: C72.2 D12.1(A) U18.2(POW+) U26.13(Q7)
NetC73_1: C73.1 R93.1
NetC73_2: C73.2 D13.1(A) U19.2(POW+) U26.14(Q6)
NetC74_1: C74.1 R94.1
NetC74_2: C74.2 D14.1(A) U20.2(POW+) U26.15(Q5)
NetC75_1: C75.1 R95.1
NetC75_2: C75.2 D15.1(A) U21.2(POW+) U26.16(Q4)
NetC76_1: C76.1 R96.1
NetC76_2: C76.2 D16.1(A) U22.2(POW+) U26.17(Q3)
NetC77_1: C77.1 R97.1
NetC77_2: C77.2 D17.1(A) U23.2(POW+) U26.18(Q2)
NetC78_1: C78.1 R98.1
NetC78_2: C78.2 D18.1(A) U24.2(POW+) U26.19(Q1)
NetC81_1: C81.1 Q1.2(B) R100.2
NetC82_1: C82.1 Q2.2(B) R102.2
NetC83_1: C83.1 Q3.2(B) R104.2
NetC84_1: C84.1 Q4.2(B) R106.2
NetC85_1: C85.1 Q5.2(B) R108.2
NetC86_1: C86.1 Q6.2(B) R110.2
NetC87_1: C87.1 Q7.2(B) R112.2
NetC88_1: C88.1 Q8.2(B) R114.2
NetQ1_1: Q1.1(C) R101.1
NetQ2_1: Q2.1(C) R103.1
NetQ3_1: Q3.1(C) R105.1
NetQ4_1: Q4.1(C) R107.1
NetQ5_1: Q5.1(C) R109.1
NetQ6_1: Q6.1(C) R111.1
NetQ7_1: Q7.1(C) R113.1
NetQ8_1: Q8.1(C) R115.1

Not connected (* = marked no-connect by the designer): U9 1(OUT); U10 1(OUT); U11 1(OUT); U12 1(OUT); U13 1(OUT); U14 1(OUT); U15 1(OUT); U16 1(OUT); U17 1(OUT); U18 1(OUT); U19 1(OUT); U20 1(OUT); U21 1(OUT); U22 1(OUT); U23 1(OUT); U24 1(OUT)

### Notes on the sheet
- 5V/15mA
- Max operating voltage: 60VDC
- 27V/20mA
- Max operating current: 1A
- 5V OC
- SS12, Ge, 0.2V
- (near C88) Not fixed
- 3.3VTTL to 5VTTL

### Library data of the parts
C61-C68 C71-C78 C81-C88 = Cap Semi: Capacitor (Semiconductor SIM Model)
D1-D8 D11-D18 = Diode: Default Diode
Q1-Q8 = QNPN: NPN Bipolar Transistor
R81-R88 R91-R98 R100-R115 = Res Semi: Semiconductor Resistor

## Sheet digit_in.SchDoc
size A3
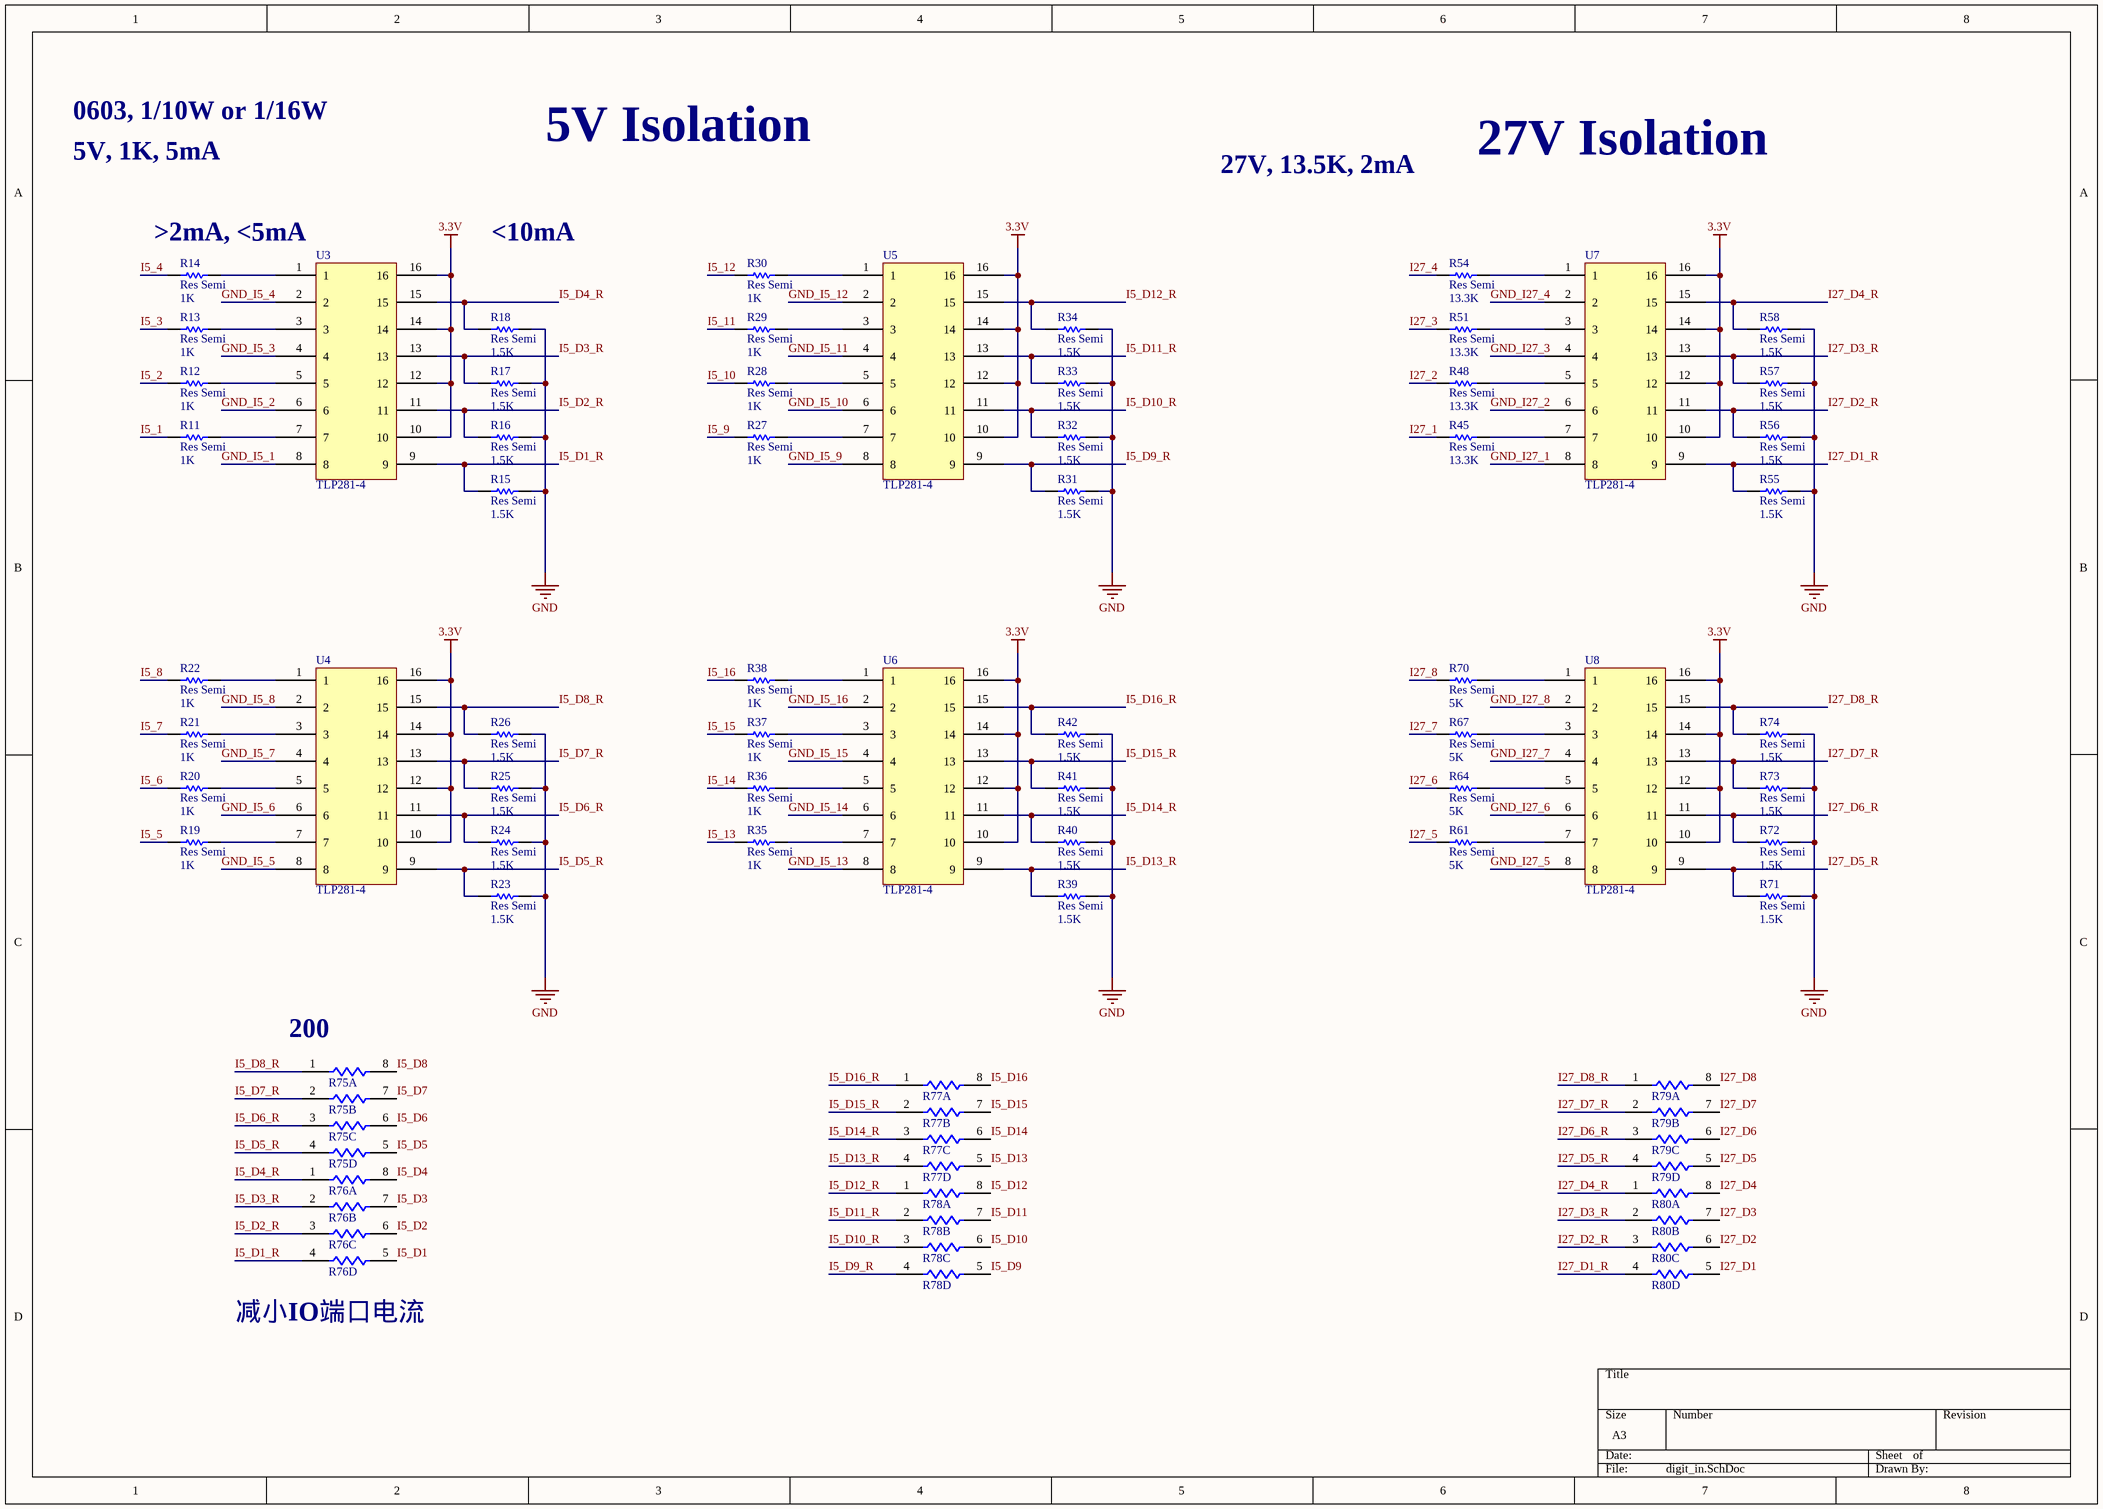
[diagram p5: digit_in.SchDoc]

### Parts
R11  Res Semi  value 1K  [1608[0603]]
R12  Res Semi  value 1K  [1608[0603]]
R13  Res Semi  value 1K  [1608[0603]]
R14  Res Semi  value 1K  [1608[0603]]
R15  Res Semi  value 1.5K  [1608[0603]]
R16  Res Semi  value 1.5K  [1608[0603]]
R17  Res Semi  value 1.5K  [1608[0603]]
R18  Res Semi  value 1.5K  [1608[0603]]
R19  Res Semi  value 1K  [1608[0603]]
R20  Res Semi  value 1K  [1608[0603]]
R21  Res Semi  value 1K  [1608[0603]]
R22  Res Semi  value 1K  [1608[0603]]
R23  Res Semi  value 1.5K  [1608[0603]]
R24  Res Semi  value 1.5K  [1608[0603]]
R25  Res Semi  value 1.5K  [1608[0603]]
R26  Res Semi  value 1.5K  [1608[0603]]
R27  Res Semi  value 1K  [1608[0603]]
R28  Res Semi  value 1K  [1608[0603]]
R29  Res Semi  value 1K  [1608[0603]]
R30  Res Semi  value 1K  [1608[0603]]
R31  Res Semi  value 1.5K  [1608[0603]]
R32  Res Semi  value 1.5K  [1608[0603]]
R33  Res Semi  value 1.5K  [1608[0603]]
R34  Res Semi  value 1.5K  [1608[0603]]
R35  Res Semi  value 1K  [1608[0603]]
R36  Res Semi  value 1K  [1608[0603]]
R37  Res Semi  value 1K  [1608[0603]]
R38  Res Semi  value 1K  [1608[0603]]
R39  Res Semi  value 1.5K  [1608[0603]]
R40  Res Semi  value 1.5K  [1608[0603]]
R41  Res Semi  value 1.5K  [1608[0603]]
R42  Res Semi  value 1.5K  [1608[0603]]
R45  Res Semi  value 13.3K  [1608[0603]]
R48  Res Semi  value 13.3K  [1608[0603]]
R51  Res Semi  value 13.3K  [1608[0603]]
R54  Res Semi  value 13.3K  [1608[0603]]
R55  Res Semi  value 1.5K  [1608[0603]]
R56  Res Semi  value 1.5K  [1608[0603]]
R57  Res Semi  value 1.5K  [1608[0603]]
R58  Res Semi  value 1.5K  [1608[0603]]
R61  Res Semi  value 5K  [1608[0603]]
R64  Res Semi  value 5K  [1608[0603]]
R67  Res Semi  value 5K  [1608[0603]]
R70  Res Semi  value 5K  [1608[0603]]
R71  Res Semi  value 1.5K  [1608[0603]]
R72  Res Semi  value 1.5K  [1608[0603]]
R73  Res Semi  value 1.5K  [1608[0603]]
R74  Res Semi  value 1.5K  [1608[0603]]
R75  R0603_4  [R0603_4]  (value not drawn)  (parts A,B,C,D of 4)
R76  R0603_4  [R0603_4]  (value not drawn)  (parts A,B,C,D of 4)
R77  R0603_4  [R0603_4]  (value not drawn)  (parts A,B,C,D of 4)
R78  R0603_4  [R0603_4]  (value not drawn)  (parts A,B,C,D of 4)
R79  R0603_4  [R0603_4]  (value not drawn)  (parts A,B,C,D of 4)
R80  R0603_4  [R0603_4]  (value not drawn)  (parts A,B,C,D of 4)
U3  TLP281-4  [TLP281-4]
U4  TLP281-4  [TLP281-4]
U5  TLP281-4  [TLP281-4]
U6  TLP281-4  [TLP281-4]
U7  TLP281-4  [TLP281-4]
U8  TLP281-4  [TLP281-4]

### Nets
3.3V: U3.10 U3.12 U3.14 U3.16 U4.10 U4.12 U4.14 U4.16 U5.10 U5.12 U5.14 U5.16 U6.10 U6.12 U6.14 U6.16 U7.10 U7.12 U7.14 U7.16 U8.10 U8.12 U8.14 U8.16
GND: R15.2 R16.2 R17.2 R18.2 R23.2 R24.2 R25.2 R26.2 R31.2 R32.2 R33.2 R34.2 R39.2 R40.2 R41.2 R42.2 R55.2 R56.2 R57.2 R58.2 R71.2 R72.2 R73.2 R74.2
GND_I5_1: U3.8
GND_I5_2: U3.6
GND_I5_3: U3.4
GND_I5_4: U3.2
GND_I5_5: U4.8
GND_I5_6: U4.6
GND_I5_7: U4.4
GND_I5_8: U4.2
GND_I5_9: U5.8
GND_I5_10: U5.6
GND_I5_11: U5.4
GND_I5_12: U5.2
GND_I5_13: U6.8
GND_I5_14: U6.6
GND_I5_15: U6.4
GND_I5_16: U6.2
GND_I27_1: U7.8
GND_I27_2: U7.6
GND_I27_3: U7.4
GND_I27_4: U7.2
GND_I27_5: U8.8
GND_I27_6: U8.6
GND_I27_7: U8.4
GND_I27_8: U8.2
I5_1: R11.1
I5_2: R12.1
I5_3: R13.1
I5_4: R14.1
I5_5: R19.1
I5_6: R20.1
I5_7: R21.1
I5_8: R22.1
I5_9: R27.1
I5_10: R28.1
I5_11: R29.1
I5_12: R30.1
I5_13: R35.1
I5_14: R36.1
I5_15: R37.1
I5_16: R38.1
I5_D1: R76.5
I5_D1_R: R15.1 R76.4 U3.9
I5_D2: R76.6
I5_D2_R: R16.1 R76.3 U3.11
I5_D3: R76.7
I5_D3_R: R17.1 R76.2 U3.13
I5_D4: R76.8
I5_D4_R: R18.1 R76.1 U3.15
I5_D5: R75.5
I5_D5_R: R23.1 R75.4 U4.9
I5_D6: R75.6
I5_D6_R: R24.1 R75.3 U4.11
I5_D7: R75.7
I5_D7_R: R25.1 R75.2 U4.13
I5_D8: R75.8
I5_D8_R: R26.1 R75.1 U4.15
I5_D9: R78.5
I5_D9_R: R31.1 R78.4 U5.9
I5_D10: R78.6
I5_D10_R: R32.1 R78.3 U5.11
I5_D11: R78.7
I5_D11_R: R33.1 R78.2 U5.13
I5_D12: R78.8
I5_D12_R: R34.1 R78.1 U5.15
I5_D13: R77.5
I5_D13_R: R39.1 R77.4 U6.9
I5_D14: R77.6
I5_D14_R: R40.1 R77.3 U6.11
I5_D15: R77.7
I5_D15_R: R41.1 R77.2 U6.13
I5_D16: R77.8
I5_D16_R: R42.1 R77.1 U6.15
I27_1: R45.1
I27_2: R48.1
I27_3: R51.1
I27_4: R54.1
I27_5: R61.1
I27_6: R64.1
I27_7: R67.1
I27_8: R70.1
I27_D1: R80.5
I27_D1_R: R55.1 R80.4 U7.9
I27_D2: R80.6
I27_D2_R: R56.1 R80.3 U7.11
I27_D3: R80.7
I27_D3_R: R57.1 R80.2 U7.13
I27_D4: R80.8
I27_D4_R: R58.1 R80.1 U7.15
I27_D5: R79.5
I27_D5_R: R71.1 R79.4 U8.9
I27_D6: R79.6
I27_D6_R: R72.1 R79.3 U8.11
I27_D7: R79.7
I27_D7_R: R73.1 R79.2 U8.13
I27_D8: R79.8
I27_D8_R: R74.1 R79.1 U8.15
NetR11_2: R11.2 U3.7
NetR12_2: R12.2 U3.5
NetR13_2: R13.2 U3.3
NetR14_2: R14.2 U3.1
NetR19_2: R19.2 U4.7
NetR20_2: R20.2 U4.5
NetR21_2: R21.2 U4.3
NetR22_2: R22.2 U4.1
NetR27_2: R27.2 U5.7
NetR28_2: R28.2 U5.5
NetR29_2: R29.2 U5.3
NetR30_2: R30.2 U5.1
NetR35_2: R35.2 U6.7
NetR36_2: R36.2 U6.5
NetR37_2: R37.2 U6.3
NetR38_2: R38.2 U6.1
NetR45_2: R45.2 U7.7
NetR48_2: R48.2 U7.5
NetR51_2: R51.2 U7.3
NetR54_2: R54.2 U7.1
NetR61_2: R61.2 U8.7
NetR64_2: R64.2 U8.5
NetR67_2: R67.2 U8.3
NetR70_2: R70.2 U8.1

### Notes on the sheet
- 0603, 1/10W or 1/16W
- 5V, 1K, 5mA
- 5V Isolation
- 27V, 13.5K, 2mA
- 27V Isolation
- >2mA, <5mA
- <10mA
- (near R75) 200
- (near R76) 减小IO端口电流

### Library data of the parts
R11-R42 R45 R48 R51 R54-R58 R61 R64 R67 R70-R74 = Res Semi: Semiconductor Resistor
R75-R80 = R0603_4: Resistor Array - Parts; Code - JEDEC: MS-012-AC; Code - IPC: SO16; Value: 33

## Sheet pxi.SchDoc
size A3
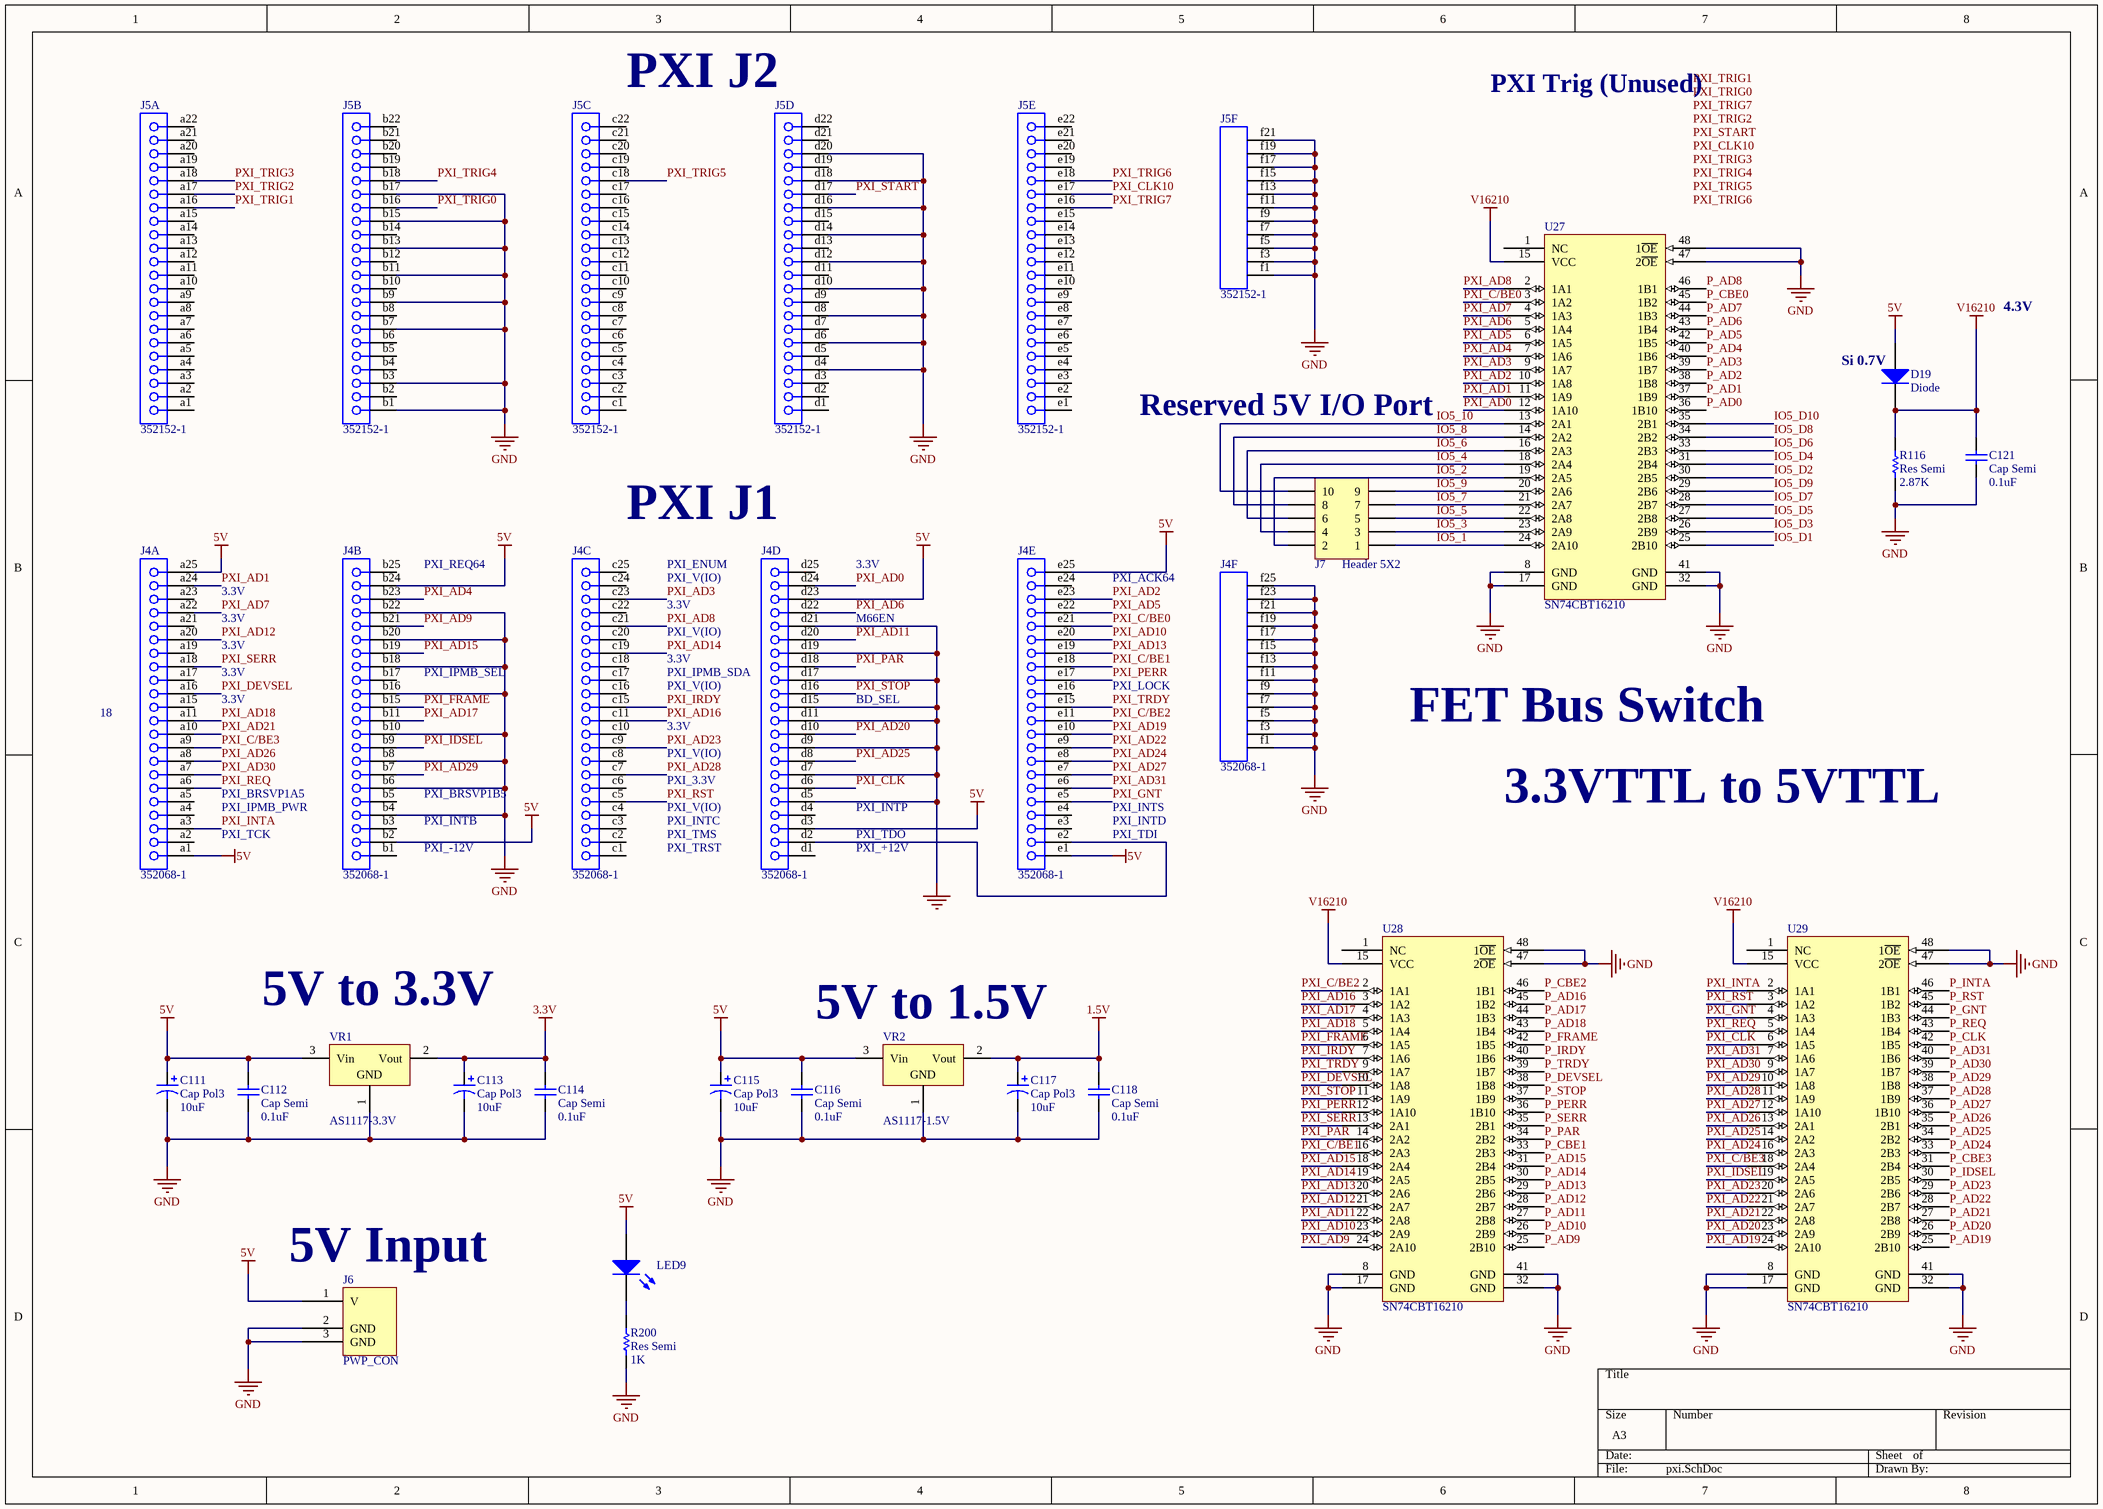
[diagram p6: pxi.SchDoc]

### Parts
C111  Cap Pol3  value 10uF  [CC3216-1206]
C112  Cap Semi  value 0.1uF  [1608[0603]]
C113  Cap Pol3  value 10uF  [CC3216-1206]
C114  Cap Semi  value 0.1uF  [1608[0603]]
C115  Cap Pol3  value 10uF  [CC3216-1206]
C116  Cap Semi  value 0.1uF  [1608[0603]]
C117  Cap Pol3  value 10uF  [CC3216-1206]
C118  Cap Semi  value 0.1uF  [1608[0603]]
C121  Cap Semi  value 0.1uF  [1608[0603]]
D19  Diode  [D1608-0603]
J4  352068-1  [BTB2-H135F]  (parts A,B,C,D,E,F of 6)
J5  352152-1  [BTB2-H132FA]  (parts A,B,C,D,E,F of 6)
J6  PWP_CON  [POWER_CON_EXTERN]
J7  Header 5X2  [HDR2X5]
LED9  LED2  [D1608-0603]  (value not drawn)
R116  Res Semi  value 2.87K  [1608[0603]]
R200  Res Semi  value 1K  [1608[0603]]
U27  SN74CBT16210  [SSOP48]
U28  SN74CBT16210  [SSOP48]
U29  SN74CBT16210  [SSOP48]
VR1  AS1117-3.3V  [LM1117]
VR2  AS1117-1.5V  [LM1117]

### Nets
1.5V: C117.1 C118.2 VR2.2(Vout)
3.3V: C113.1 C114.2 VR1.2(Vout)
5V: C111.1 C112.2 C115.1 C116.2 D19.1(A) J4.a1 J4.a25 J4.b2 J4.b24 J4.d3 J4.d23 J4.e1 J4.e25 J6.1(V) LED9.1(A) VR1.3(Vin) VR2.3(Vin)
GND: C111.2 C112.1 C113.2 C114.1 C115.2 C116.1 C117.2 C118.1 C121.1 J4.b4 J4.b6 J4.b8 J4.b10 J4.b16 J4.b18 J4.b20 J4.b22 J4.d5 J4.d7 J4.d9 J4.d11 J4.d15 J4.d17 J4.d19 J4.d21 J4.f1 J4.f3 J4.f5 J4.f7 J4.f9 J4.f11 J4.f13 J4.f15 J4.f17 J4.f19 J4.f21 J4.f23 J4.f25 J5.b1 J5.b3 J5.b7 J5.b9 J5.b11 J5.b13 J5.b15 J5.b17 J5.d4 J5.d6 J5.d8 J5.d10 J5.d12 J5.d14 J5.d16 J5.d18 J5.d20 J5.f1 J5.f3 J5.f5 J5.f7 J5.f9 J5.f11 J5.f13 J5.f15 J5.f17 J5.f19 J5.f21 J6.2(GND) J6.3(GND) R116.1 R200.1 U27.8(GND) U27.17(GND) U27.32(GND) U27.41(GND) U27.47(2~{OE}) U27.48(1~{OE}) U28.8(GND) U28.17(GND) U28.32(GND) U28.41(GND) U28.47(2~{OE}) U28.48(1~{OE}) U29.8(GND) U29.17(GND) U29.32(GND) U29.41(GND) U29.47(2~{OE}) U29.48(1~{OE}) VR1.1(GND) VR2.1(GND)
V16210: C121.2 D19.2(K) R116.2 U27.15(VCC) U28.15(VCC) U29.15(VCC)
IO5_1: J7.1 U27.24(2A10)
IO5_2: J7.2 U27.19(2A5)
IO5_3: J7.3 U27.23(2A9)
IO5_4: J7.4 U27.18(2A4)
IO5_5: J7.5 U27.22(2A8)
IO5_6: J7.6 U27.16(2A3)
IO5_7: J7.7 U27.21(2A7)
IO5_8: J7.8 U27.14(2A2)
IO5_9: J7.9 U27.20(2A6)
IO5_10: J7.10 U27.13(2A1)
IO5_D1: U27.25(2B10)
IO5_D2: U27.30(2B5)
IO5_D3: U27.26(2B9)
IO5_D4: U27.31(2B4)
IO5_D5: U27.27(2B8)
IO5_D6: U27.33(2B3)
IO5_D7: U27.28(2B7)
IO5_D8: U27.34(2B2)
IO5_D9: U27.29(2B6)
IO5_D10: U27.35(2B1)
P_AD0: U27.36(1B10)
P_AD1: U27.37(1B9)
P_AD2: U27.38(1B8)
P_AD3: U27.39(1B7)
P_AD4: U27.40(1B6)
P_AD5: U27.42(1B5)
P_AD6: U27.43(1B4)
P_AD7: U27.44(1B3)
P_AD8: U27.46(1B1)
P_AD9: U28.25(2B10)
P_AD10: U28.26(2B9)
P_AD11: U28.27(2B8)
P_AD12: U28.28(2B7)
P_AD13: U28.29(2B6)
P_AD14: U28.30(2B5)
P_AD15: U28.31(2B4)
P_AD16: U28.45(1B2)
P_AD17: U28.44(1B3)
P_AD18: U28.43(1B4)
P_AD19: U29.25(2B10)
P_AD20: U29.26(2B9)
P_AD21: U29.27(2B8)
P_AD22: U29.28(2B7)
P_AD23: U29.29(2B6)
P_AD24: U29.33(2B3)
P_AD25: U29.34(2B2)
P_AD26: U29.35(2B1)
P_AD27: U29.36(1B10)
P_AD28: U29.37(1B9)
P_AD29: U29.38(1B8)
P_AD30: U29.39(1B7)
P_AD31: U29.40(1B6)
P_CBE0: U27.45(1B2)
P_CBE1: U28.33(2B3)
P_CBE2: U28.46(1B1)
P_CBE3: U29.31(2B4)
P_CLK: U29.42(1B5)
P_DEVSEL: U28.38(1B8)
P_FRAME: U28.42(1B5)
P_GNT: U29.44(1B3)
P_IDSEL: U29.30(2B5)
P_INTA: U29.46(1B1)
P_IRDY: U28.40(1B6)
P_PAR: U28.34(2B2)
P_PERR: U28.36(1B10)
P_REQ: U29.43(1B4)
P_RST: U29.45(1B2)
P_SERR: U28.35(2B1)
P_STOP: U28.37(1B9)
P_TRDY: U28.39(1B7)
PXI_AD0: J4.d24 U27.12(1A10)
PXI_AD1: J4.a24 U27.11(1A9)
PXI_AD2: J4.e23 U27.10(1A8)
PXI_AD3: J4.c23 U27.9(1A7)
PXI_AD4: J4.b23 U27.7(1A6)
PXI_AD5: J4.e22 U27.6(1A5)
PXI_AD6: J4.d22 U27.5(1A4)
PXI_AD7: J4.a22 U27.4(1A3)
PXI_AD8: J4.c21 U27.2(1A1)
PXI_AD9: J4.b21 U28.24(2A10)
PXI_AD10: J4.e20 U28.23(2A9)
PXI_AD11: J4.d20 U28.22(2A8)
PXI_AD12: J4.a20 U28.21(2A7)
PXI_AD13: J4.e19 U28.20(2A6)
PXI_AD14: J4.c19 U28.19(2A5)
PXI_AD15: J4.b19 U28.18(2A4)
PXI_AD16: J4.c11 U28.3(1A2)
PXI_AD17: J4.b11 U28.4(1A3)
PXI_AD18: J4.a11 U28.5(1A4)
PXI_AD19: J4.e10 U29.24(2A10)
PXI_AD20: J4.d10 U29.23(2A9)
PXI_AD21: J4.a10 U29.22(2A8)
PXI_AD22: J4.e9 U29.21(2A7)
PXI_AD23: J4.c9 U29.20(2A6)
PXI_AD24: J4.e8 U29.16(2A3)
PXI_AD25: J4.d8 U29.14(2A2)
PXI_AD26: J4.a8 U29.13(2A1)
PXI_AD27: J4.e7 U29.12(1A10)
PXI_AD28: J4.c7 U29.11(1A9)
PXI_AD29: J4.b7 U29.10(1A8)
PXI_AD30: J4.a7 U29.9(1A7)
PXI_AD31: J4.e6 U29.7(1A6)
PXI_C/BE0: J4.e21 U27.3(1A2)
PXI_C/BE1: J4.e18 U28.16(2A3)
PXI_C/BE2: J4.e11 U28.2(1A1)
PXI_C/BE3: J4.a9 U29.18(2A4)
PXI_CLK: J4.d6 U29.6(1A5)
PXI_CLK10: J5.e17
PXI_DEVSEL: J4.a16 U28.10(1A8)
PXI_FRAME: J4.b15 U28.6(1A5)
PXI_GNT: J4.e5 U29.4(1A3)
PXI_IDSEL: J4.b9 U29.19(2A5)
PXI_INTA: J4.a3 U29.2(1A1)
PXI_IRDY: J4.c15 U28.7(1A6)
PXI_PAR: J4.d18 U28.14(2A2)
PXI_PERR: J4.e17 U28.12(1A10)
PXI_REQ: J4.a6 U29.5(1A4)
PXI_RST: J4.c5 U29.3(1A2)
PXI_SERR: J4.a18 U28.13(2A1)
PXI_START: J5.d17
PXI_STOP: J4.d16 U28.11(1A9)
PXI_TRDY: J4.e15 U28.9(1A7)
PXI_TRIG0: J5.b16
PXI_TRIG1: J5.a16
PXI_TRIG2: J5.a17
PXI_TRIG3: J5.a18
PXI_TRIG4: J5.b18
PXI_TRIG5: J5.c18
PXI_TRIG6: J5.e18
PXI_TRIG7: J5.e16
NetJ4_d2: J4.d2 J4.e2
NetLED9_2: LED9.2(K) R200.2

Not connected (* = marked no-connect by the designer): J4 a2 a4 a5 a15 a17 a19 a21 a23 b1 b3 b5 b17 b25 c1 c2 c3 c4 c6 c8 c10 c16 c17 c18 c20 c22 c24 c25 d1 d4 d25 e3 e4 e16 e24; J5 a1 a2 a3 a4 a5 a6 a7 a8 a9 a10 a11 a12 a13 a14 a15 a19 a20 a21 a22 b2 b4 b5 b6 b8 b10 b12 b14 b19 b20 b21 b22 c1 c2 c3 c4 c5 c6 c7 c8 c9 c10 c11 c12 c13 c14 c15 c16 c17 c19 c20 c21 c22 d1 d2 d3 d5 d7 d9 d11 d13 d15 d19 d21 d22 e1 e2 e3 e4 e5 e6 e7 e8 e9 e10 e11 e12 e13 e14 e15 e19 e20 e21 e22; U27 1(NC); U28 1(NC); U29 1(NC)

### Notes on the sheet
- (near J5) PXI J2
- PXI Trig (Unused)
- 4.3V
- (near D19) Si 0.7V
- Reserved 5V I/O Port
- PXI_REQ64
- (near J4) PXI J1
- PXI_ENUM
- PXI_V(IO)
- 3.3V
- PXI_ACK64
- M66EN
- 18
- PXI_IPMB_SEL
- (near J4) PXI_IPMB_SDA
- BD_SEL
- PXI_LOCK
- PXI_3.3V
- FET Bus Switch
- PXI_TCK
- PXI_IPMB_PWR
- PXI_BRSVP1A5
- PXI_BRSVP1B5
- PXI_INTB
- PXI_-12V
- PXI_INTC
- PXI_TMS
- PXI_TRST
- PXI_INTP
- PXI_+12V
- PXI_TDO
- PXI_INTS
- PXI_INTD
- PXI_TDI
- 3.3VTTL to 5VTTL
- (near VR1) 5V to 3.3V
- (near VR2) 5V to 1.5V
- (near J6) 5V Input
- Labels drawn without touching a wire or pin: PXI_CLK10, PXI_START, PXI_TRIG0, PXI_TRIG1, PXI_TRIG2, PXI_TRIG3, PXI_TRIG4, PXI_TRIG5, PXI_TRIG6, PXI_TRIG7

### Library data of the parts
C111 C113 C115 C117 = Cap Pol3: Polarized Capacitor (Surface Mount)
C112 C114 C116 C118 C121 = Cap Semi: Capacitor (Semiconductor SIM Model)
D19 = Diode: Default Diode
J4 = 352068-1: Z-Pack 2mm Hard Metric Type A 110 Position Female PCB Mount Connector; Positions: 110; ComponentLength: 50 mm; MatingPolarization: Multi-Purpose Center; RowsLoaded: A, B, D, C, E; PCB_Layout: Complies with manufacturer's recommendation.; DrillSize: Corresponds to nominal value.
J5 = 352152-1: Z-Pack 2mm Hard Metric Type B 110 Position Female Daughter Card Connector; Positions: 110; ComponentLength: 44 mm; MatingPolarization: None; RowsLoaded: A, B, D, C, E; PCB_Layout: Complies with manufacturer's recommendation.; DrillSize: Corresponds to nominal value.
J7 = Header 5X2: Header, 5-Pin, Dual row
LED9 = LED2: as LED1 on sheet fpga
R116 R200 = Res Semi: Semiconductor Resistor
VR1 VR2 = Volt Reg: Voltage Regulator; Code - JEDEC: SMD-220

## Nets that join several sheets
1.5V: fpga (26 pins), pxi (C117.1 C118.2 VR2.2)
3.3V: fpga (43 pins), digit_in (24 pins), pxi (C113.1 C114.2 VR1.2)
5V: pxi_io (J1.25 J1.26 J1.75 J1.76), digit_out (50 pins), pxi (17 pins)
GND: pxi_io (J1.77 J1.78 J1.79 J1.80), fpga (83 pins), digit_out (10 pins), digit_in (24 pins), pxi (90 pins)
GND_I5_1: pxi_io (J1.60), digit_in (U3.8)
GND_I5_2: pxi_io (J1.62), digit_in (U3.6)
GND_I5_3: pxi_io (J1.64), digit_in (U3.4)
GND_I5_4: pxi_io (J1.66), digit_in (U3.2)
GND_I5_5: pxi_io (J1.10), digit_in (U4.8)
GND_I5_6: pxi_io (J1.12), digit_in (U4.6)
GND_I5_7: pxi_io (J1.14), digit_in (U4.4)
GND_I5_8: pxi_io (J1.16), digit_in (U4.2)
GND_I5_9: pxi_io (J1.68), digit_in (U5.8)
GND_I5_10: pxi_io (J1.70), digit_in (U5.6)
GND_I5_11: pxi_io (J1.72), digit_in (U5.4)
GND_I5_12: pxi_io (J1.74), digit_in (U5.2)
GND_I5_13: pxi_io (J1.18), digit_in (U6.8)
GND_I5_14: pxi_io (J1.20), digit_in (U6.6)
GND_I5_15: pxi_io (J1.22), digit_in (U6.4)
GND_I5_16: pxi_io (J1.24), digit_in (U6.2)
GND_I27_1: pxi_io (J1.58), digit_in (U7.8)
GND_I27_2: pxi_io (J1.56), digit_in (U7.6)
GND_I27_3: pxi_io (J1.54), digit_in (U7.4)
GND_I27_4: pxi_io (J1.52), digit_in (U7.2)
GND_I27_5: pxi_io (J1.2), digit_in (U8.8)
GND_I27_6: pxi_io (J1.4), digit_in (U8.6)
GND_I27_7: pxi_io (J1.6), digit_in (U8.4)
GND_I27_8: pxi_io (J1.8), digit_in (U8.2)
I5_1: pxi_io (J1.59), digit_in (R11.1)
I5_2: pxi_io (J1.61), digit_in (R12.1)
I5_3: pxi_io (J1.63), digit_in (R13.1)
I5_4: pxi_io (J1.65), digit_in (R14.1)
I5_5: pxi_io (J1.9), digit_in (R19.1)
I5_6: pxi_io (J1.11), digit_in (R20.1)
I5_7: pxi_io (J1.13), digit_in (R21.1)
I5_8: pxi_io (J1.15), digit_in (R22.1)
I5_9: pxi_io (J1.67), digit_in (R27.1)
I5_10: pxi_io (J1.69), digit_in (R28.1)
I5_11: pxi_io (J1.71), digit_in (R29.1)
I5_12: pxi_io (J1.73), digit_in (R30.1)
I5_13: pxi_io (J1.17), digit_in (R35.1)
I5_14: pxi_io (J1.19), digit_in (R36.1)
I5_15: pxi_io (J1.21), digit_in (R37.1)
I5_16: pxi_io (J1.23), digit_in (R38.1)
I5_D1: fpga (U1.18), digit_in (R76.5)
I5_D2: fpga (U1.17), digit_in (R76.6)
I5_D3: fpga (U1.16), digit_in (R76.7)
I5_D4: fpga (U1.15), digit_in (R76.8)
I5_D5: fpga (U1.14), digit_in (R75.5)
I5_D6: fpga (U1.13), digit_in (R75.6)
I5_D7: fpga (U1.12), digit_in (R75.7)
I5_D8: fpga (U1.11), digit_in (R75.8)
I5_D9: fpga (U1.8), digit_in (R78.5)
I5_D10: fpga (U1.7), digit_in (R78.6)
I5_D11: fpga (U1.6), digit_in (R78.7)
I5_D12: fpga (U1.5), digit_in (R78.8)
I5_D13: fpga (U1.4), digit_in (R77.5)
I5_D14: fpga (U1.3), digit_in (R77.6)
I5_D15: fpga (U1.2), digit_in (R77.7)
I5_D16: fpga (U1.1), digit_in (R77.8)
I27_1: pxi_io (J1.57), digit_in (R45.1)
I27_2: pxi_io (J1.55), digit_in (R48.1)
I27_3: pxi_io (J1.53), digit_in (R51.1)
I27_4: pxi_io (J1.51), digit_in (R54.1)
I27_5: pxi_io (J1.1), digit_in (R61.1)
I27_6: pxi_io (J1.3), digit_in (R64.1)
I27_7: pxi_io (J1.5), digit_in (R67.1)
I27_8: pxi_io (J1.7), digit_in (R70.1)
I27_D1: fpga (U1.60), digit_in (R80.5)
I27_D2: fpga (U1.59), digit_in (R80.6)
I27_D3: fpga (U1.58), digit_in (R80.7)
I27_D4: fpga (U1.57), digit_in (R80.8)
I27_D5: fpga (U1.56), digit_in (R79.5)
I27_D6: fpga (U1.55), digit_in (R79.6)
I27_D7: fpga (U1.54), digit_in (R79.7)
I27_D8: fpga (U1.53), digit_in (R79.8)
IO5_D1: fpga (U1.180), pxi (U27.25)
IO5_D2: fpga (U1.175), pxi (U27.30)
IO5_D3: fpga (U1.179), pxi (U27.26)
IO5_D4: fpga (U1.174), pxi (U27.31)
IO5_D5: fpga (U1.178), pxi (U27.27)
IO5_D6: fpga (U1.173), pxi (U27.33)
IO5_D7: fpga (U1.177), pxi (U27.28)
IO5_D8: fpga (U1.170), pxi (U27.34)
IO5_D9: fpga (U1.176), pxi (U27.29)
IO5_D10: fpga (U1.169), pxi (U27.35)
O5_1_A: pxi_io (J1.39), digit_out (U9.5 U9.6)
O5_1_B: pxi_io (J1.96), digit_out (U9.10)
O5_2_A: pxi_io (J1.40), digit_out (U10.5 U10.6)
O5_2_B: pxi_io (J1.95), digit_out (U10.10)
O5_3_A: pxi_io (J1.89), digit_out (U11.5 U11.6)
O5_3_B: pxi_io (J1.45), digit_out (U11.10)
O5_4_A: pxi_io (J1.90), digit_out (U12.5 U12.6)
O5_4_B: pxi_io (J1.46), digit_out (U12.10)
O5_5_A: pxi_io (J1.41), digit_out (U13.5 U13.6)
O5_5_B: pxi_io (J1.94), digit_out (U13.10)
O5_6_A: pxi_io (J1.42), digit_out (U14.5 U14.6)
O5_6_B: pxi_io (J1.93), digit_out (U14.10)
O5_7_A: pxi_io (J1.91), digit_out (U15.5 U15.6)
O5_7_B: pxi_io (J1.44), digit_out (U15.10)
O5_8_A: pxi_io (J1.92), digit_out (U16.5 U16.6)
O5_8_B: pxi_io (J1.43), digit_out (U16.10)
O5_D1: fpga (U1.193), digit_out (U25.9)
O5_D2: fpga (U1.194), digit_out (U25.8)
O5_D3: fpga (U1.195), digit_out (U25.7)
O5_D4: fpga (U1.200), digit_out (U25.6)
O5_D5: fpga (U1.201), digit_out (U25.5)
O5_D6: fpga (U1.202), digit_out (U25.4)
O5_D7: fpga (U1.203), digit_out (U25.3)
O5_D8: fpga (U1.206), digit_out (U25.2)
O5_LE: fpga (U1.208), digit_out (U25.11)
O5_OE: fpga (U1.207), digit_out (U25.1)
O27_1_A: pxi_io (J1.31), digit_out (U17.5 U17.6)
O27_1_B: pxi_io (J1.88), digit_out (U17.10)
O27_2_A: pxi_io (J1.32), digit_out (U18.5 U18.6)
O27_2_B: pxi_io (J1.87), digit_out (U18.10)
O27_3_A: pxi_io (J1.81), digit_out (U19.5 U19.6)
O27_3_B: pxi_io (J1.38), digit_out (U19.10)
O27_4_A: pxi_io (J1.82), digit_out (U20.5 U20.6)
O27_4_B: pxi_io (J1.37), digit_out (U20.10)
O27_5_A: pxi_io (J1.33), digit_out (U21.5 U21.6)
O27_5_B: pxi_io (J1.36), digit_out (U21.10)
O27_6_A: pxi_io (J1.34), digit_out (U22.5 U22.6)
O27_6_B: pxi_io (J1.86), digit_out (U22.10)
O27_7_A: pxi_io (J1.83), digit_out (U23.5 U23.6)
O27_7_B: pxi_io (J1.85), digit_out (U23.10)
O27_8_A: pxi_io (J1.84), digit_out (U24.5 U24.6)
O27_8_B: pxi_io (J1.35), digit_out (U24.10)
O27_D1: fpga (U1.214), digit_out (U26.9)
O27_D2: fpga (U1.215), digit_out (U26.8)
O27_D3: fpga (U1.216), digit_out (U26.7)
O27_D4: fpga (U1.217), digit_out (U26.6)
O27_D5: fpga (U1.218), digit_out (U26.5)
O27_D6: fpga (U1.219), digit_out (U26.4)
O27_D7: fpga (U1.222), digit_out (U26.3)
O27_D8: fpga (U1.223), digit_out (U26.2)
O27_LE: fpga (U1.225), digit_out (U26.11)
O27_OE: fpga (U1.224), digit_out (U26.1)
OC5_1: pxi_io (J1.97), digit_out (R101.2)
OC5_2: pxi_io (J1.99), digit_out (R103.2)
OC5_3: pxi_io (J1.100), digit_out (R105.2)
OC5_4: pxi_io (J1.98), digit_out (R107.2)
OC5_5: pxi_io (J1.49), digit_out (R109.2)
OC5_6: pxi_io (J1.47), digit_out (R111.2)
OC5_7: pxi_io (J1.50), digit_out (R113.2)
OC5_8: pxi_io (J1.48), digit_out (R115.2)
OC5_D1: fpga (U1.181), digit_out (C81.2 R100.1)
OC5_D2: fpga (U1.182), digit_out (C82.2 R102.1)
OC5_D3: fpga (U1.183), digit_out (C83.2 R104.1)
OC5_D4: fpga (U1.184), digit_out (C84.2 R106.1)
OC5_D5: fpga (U1.185), digit_out (C85.2 R108.1)
OC5_D6: fpga (U1.186), digit_out (C86.2 R110.1)
OC5_D7: fpga (U1.187), digit_out (C87.2 R112.1)
OC5_D8: fpga (U1.188), digit_out (C88.2 R114.1)
P_AD0: fpga (U1.167), pxi (U27.36)
P_AD1: fpga (U1.166), pxi (U27.37)
P_AD2: fpga (U1.165), pxi (U27.38)
P_AD3: fpga (U1.164), pxi (U27.39)
P_AD4: fpga (U1.163), pxi (U27.40)
P_AD5: fpga (U1.162), pxi (U27.42)
P_AD6: fpga (U1.161), pxi (U27.43)
P_AD7: fpga (U1.160), pxi (U27.44)
P_AD8: fpga (U1.158), pxi (U27.46)
P_AD9: fpga (U1.144), pxi (U28.25)
P_AD10: fpga (U1.143), pxi (U28.26)
P_AD11: fpga (U1.141), pxi (U28.27)
P_AD12: fpga (U1.140), pxi (U28.28)
P_AD13: fpga (U1.139), pxi (U28.29)
P_AD14: fpga (U1.138), pxi (U28.30)
P_AD15: fpga (U1.137), pxi (U28.31)
P_AD16: fpga (U1.122), pxi (U28.45)
P_AD17: fpga (U1.123), pxi (U28.44)
P_AD18: fpga (U1.124), pxi (U28.43)
P_AD19: fpga (U1.120), pxi (U29.25)
P_AD20: fpga (U1.119), pxi (U29.26)
P_AD21: fpga (U1.118), pxi (U29.27)
P_AD22: fpga (U1.117), pxi (U29.28)
P_AD23: fpga (U1.116), pxi (U29.29)
P_AD24: fpga (U1.113), pxi (U29.33)
P_AD25: fpga (U1.108), pxi (U29.34)
P_AD26: fpga (U1.107), pxi (U29.35)
P_AD27: fpga (U1.105), pxi (U29.36)
P_AD28: fpga (U1.104), pxi (U29.37)
P_AD29: fpga (U1.101), pxi (U29.38)
P_AD30: fpga (U1.100), pxi (U29.39)
P_AD31: fpga (U1.99), pxi (U29.40)
P_CBE0: fpga (U1.159), pxi (U27.45)
P_CBE1: fpga (U1.136), pxi (U28.33)
P_CBE2: fpga (U1.121), pxi (U28.46)
P_CBE3: fpga (U1.114), pxi (U29.31)
P_CLK: fpga (U1.29), pxi (U29.42)
P_DEVSEL: fpga (U1.128), pxi (U28.38)
P_FRAME: fpga (U1.125), pxi (U28.42)
P_GNT: fpga (U1.94), pxi (U29.44)
P_IDSEL: fpga (U1.115), pxi (U29.30)
P_INTA: fpga (U1.88), pxi (U29.46)
P_IRDY: fpga (U1.126), pxi (U28.40)
P_PAR: fpga (U1.135), pxi (U28.34)
P_PERR: fpga (U1.132), pxi (U28.36)
P_REQ: fpga (U1.95), pxi (U29.43)
P_RST: fpga (U1.28), pxi (U29.45)
P_SERR: fpga (U1.134), pxi (U28.35)
P_STOP: fpga (U1.131), pxi (U28.37)
P_TRDY: fpga (U1.127), pxi (U28.39)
